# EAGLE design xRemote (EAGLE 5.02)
CAT_NR: 04; CLASS: 5HNc; LAST_EDIT: 11.09; SHORTNAME: DulM; SUBTITLE: Stromlaufplan; TITLE: xRemote - CapSense; USERNAME: Dullnig Michael

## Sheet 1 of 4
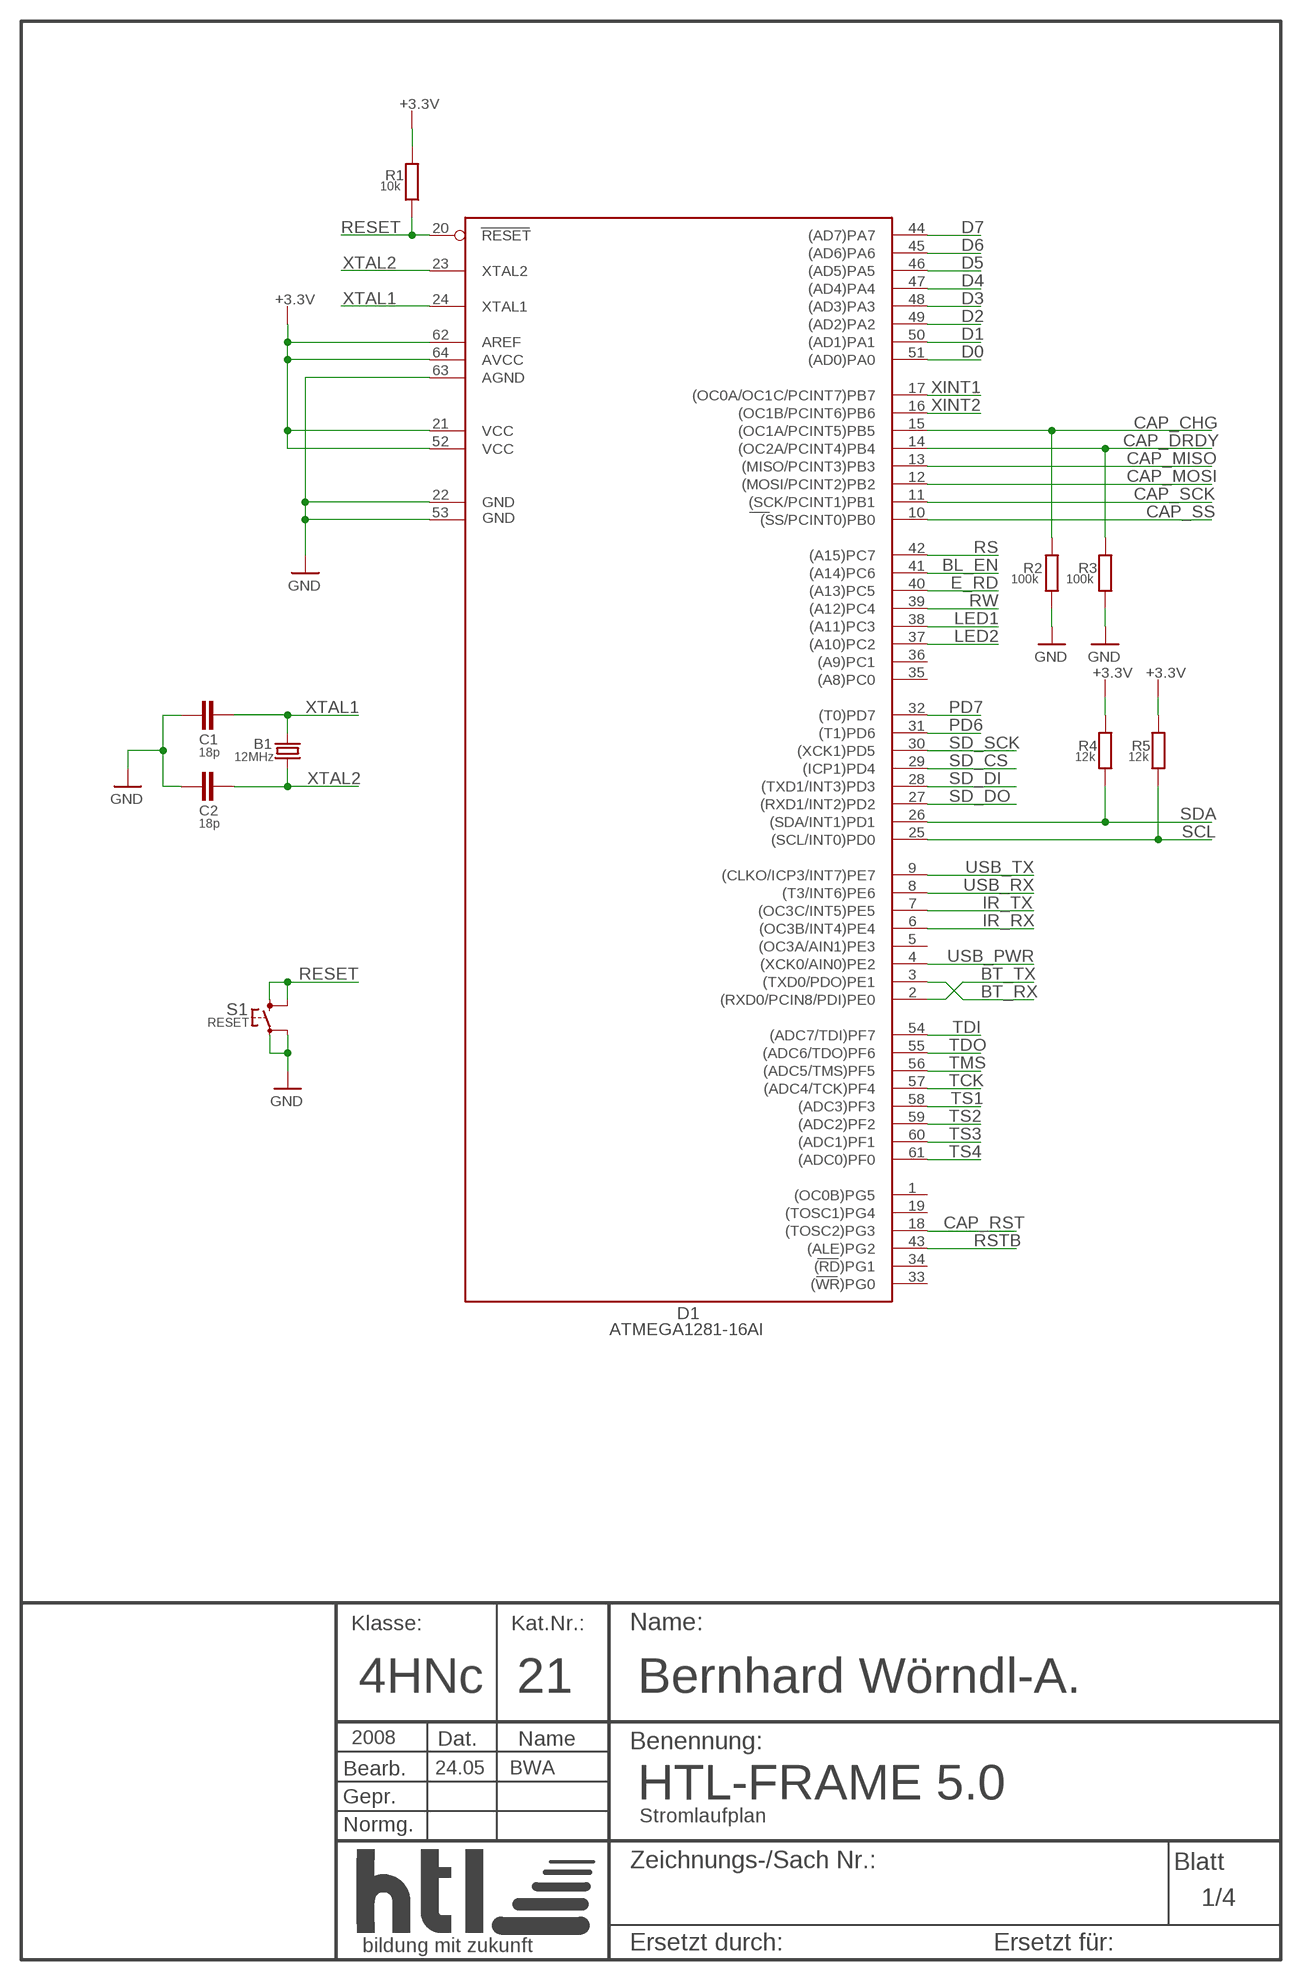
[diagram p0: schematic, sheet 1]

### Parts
B1  12MHz  CRYSTALHC49UP  [HC49UP]
C1  18p  C-EUC0805  [C0805]
C2  18p  C-EUC0805  [C0805]
D1  ATMEGA1281-16AI  ATMEGA2561-16AI  [TQFP64]
R1  10k  R-EU_M0805  [M0805]
R2  100k  R-EU_M1206  [M1206]
R3  100k  R-EU_M1206  [M1206]
R4  12k  R-EU_M1206  [M1206]
R5  12k  R-EU_M1206  [M1206]
S1  RESET  10-XX  [B3F-10XX]
U$1  HTL-FRAME-A4  [NOTHING]

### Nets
+3.3V: D1.21(VCC) D1.52(VCC1) D1.62(AREF) D1.64(AVCC) R1.2 R4.2 R5.2 ; also sheet 2,3,4
BL_EN: D1.41((A14)PC6) ; also sheet 3
BT_RX: D1.3((TXD0/PDO)PE1) ; also sheet 3
BT_TX: D1.2((RXD0/PCIN8/PDI)PE0) ; also sheet 3
CAP_CHG: D1.15((OC1A/PCINT5)PB5) R2.1 ; also sheet 4
CAP_DRDY: D1.14((OC2A/PCINT4)PB4) R3.1 ; also sheet 4
CAP_MISO: D1.13((MISO/PCINT3)PB3) ; also sheet 4
CAP_MOSI: D1.12((MOSI/PCINT2)PB2) ; also sheet 4
CAP_RST: D1.18((TOSC2)PG3) ; also sheet 4
CAP_SCK: D1.11((SCK/PCINT1)PB1) ; also sheet 4
CAP_SS: D1.10((SS/PCINT0)PB0) ; also sheet 4
D0: D1.51((AD0)PA0) ; also sheet 3
D1: D1.50((AD1)PA1) ; also sheet 3
D2: D1.49((AD2)PA2) ; also sheet 3
D3: D1.48((AD3)PA3) ; also sheet 3
D4: D1.47((AD4)PA4) ; also sheet 3
D5: D1.46((AD5)PA5) ; also sheet 3
D6: D1.45((AD6)PA6) ; also sheet 3
D7: D1.44((AD7)PA7) ; also sheet 3
E_RD: D1.40((A13)PC5) ; also sheet 3
GND: C1.1 C2.1 D1.22(GND) D1.53(GND1) D1.63(AGND) R2.2 R3.2 S1.3(P1) S1.4(P) ; also sheet 2,3,4
IR_RX: D1.6((OC3B/INT4)PE4) ; also sheet 4
IR_TX: D1.7((OC3C/INT5)PE5) ; also sheet 4
LED1: D1.38((A11)PC3) ; also sheet 3
LED2: D1.37((A10)PC2) ; also sheet 3
PD6: D1.31((T1)PD6) ; also sheet 3
PD7: D1.32((T0)PD7) ; also sheet 3
RESET: D1.20(RESET) R1.1 S1.1(S1) S1.2(S) ; also sheet 3
RS: D1.42((A15)PC7) ; also sheet 3
RSTB: D1.43((ALE)PG2) ; also sheet 3
RW: D1.39((A12)PC4) ; also sheet 3
SCL: D1.25((SCL/INT0)PD0) R5.1 ; also sheet 3
SD_CS: D1.29((ICP1)PD4) ; also sheet 3
SD_DI: D1.28((TXD1/INT3)PD3) ; also sheet 3
SD_DO: D1.27((RXD1/INT2)PD2) ; also sheet 3
SD_SCK: D1.30((XCK1)PD5) ; also sheet 3
SDA: D1.26((SDA/INT1)PD1) R4.1 ; also sheet 3
TCK: D1.57((ADC4/TCK)PF4) ; also sheet 3
TDI: D1.54((ADC7/TDI)PF7) ; also sheet 3
TDO: D1.55((ADC6/TDO)PF6) ; also sheet 3
TMS: D1.56((ADC5/TMS)PF5) ; also sheet 3
TS1: D1.58((ADC3)PF3) ; also sheet 3
TS2: D1.59((ADC2)PF2) ; also sheet 3
TS3: D1.60((ADC1)PF1) ; also sheet 3
TS4: D1.61((ADC0)PF0) ; also sheet 3
USB_PWR: D1.4((XCK0/AIN0)PE2) ; also sheet 3
USB_RX: D1.8((T3/INT6)PE6) ; also sheet 3
USB_TX: D1.9((CLKO/ICP3/INT7)PE7) ; also sheet 3
XINT1: D1.17((OC0A/OC1C/PCINT7)PB7) ; also sheet 3
XINT2: D1.16((OC1B/PCINT6)PB6) ; also sheet 3
XTAL1: B1.2 C1.2 D1.24(XTAL1)
XTAL2: B1.1 C2.2 D1.23(XTAL2)
Unconnected: D1.1((OC0B)PG5) D1.5((OC3A/AIN1)PE3) D1.19((TOSC1)PG4) D1.33((WR)PG0) D1.34((RD)PG1) D1.35((A8)PC0) D1.36((A9)PC1)

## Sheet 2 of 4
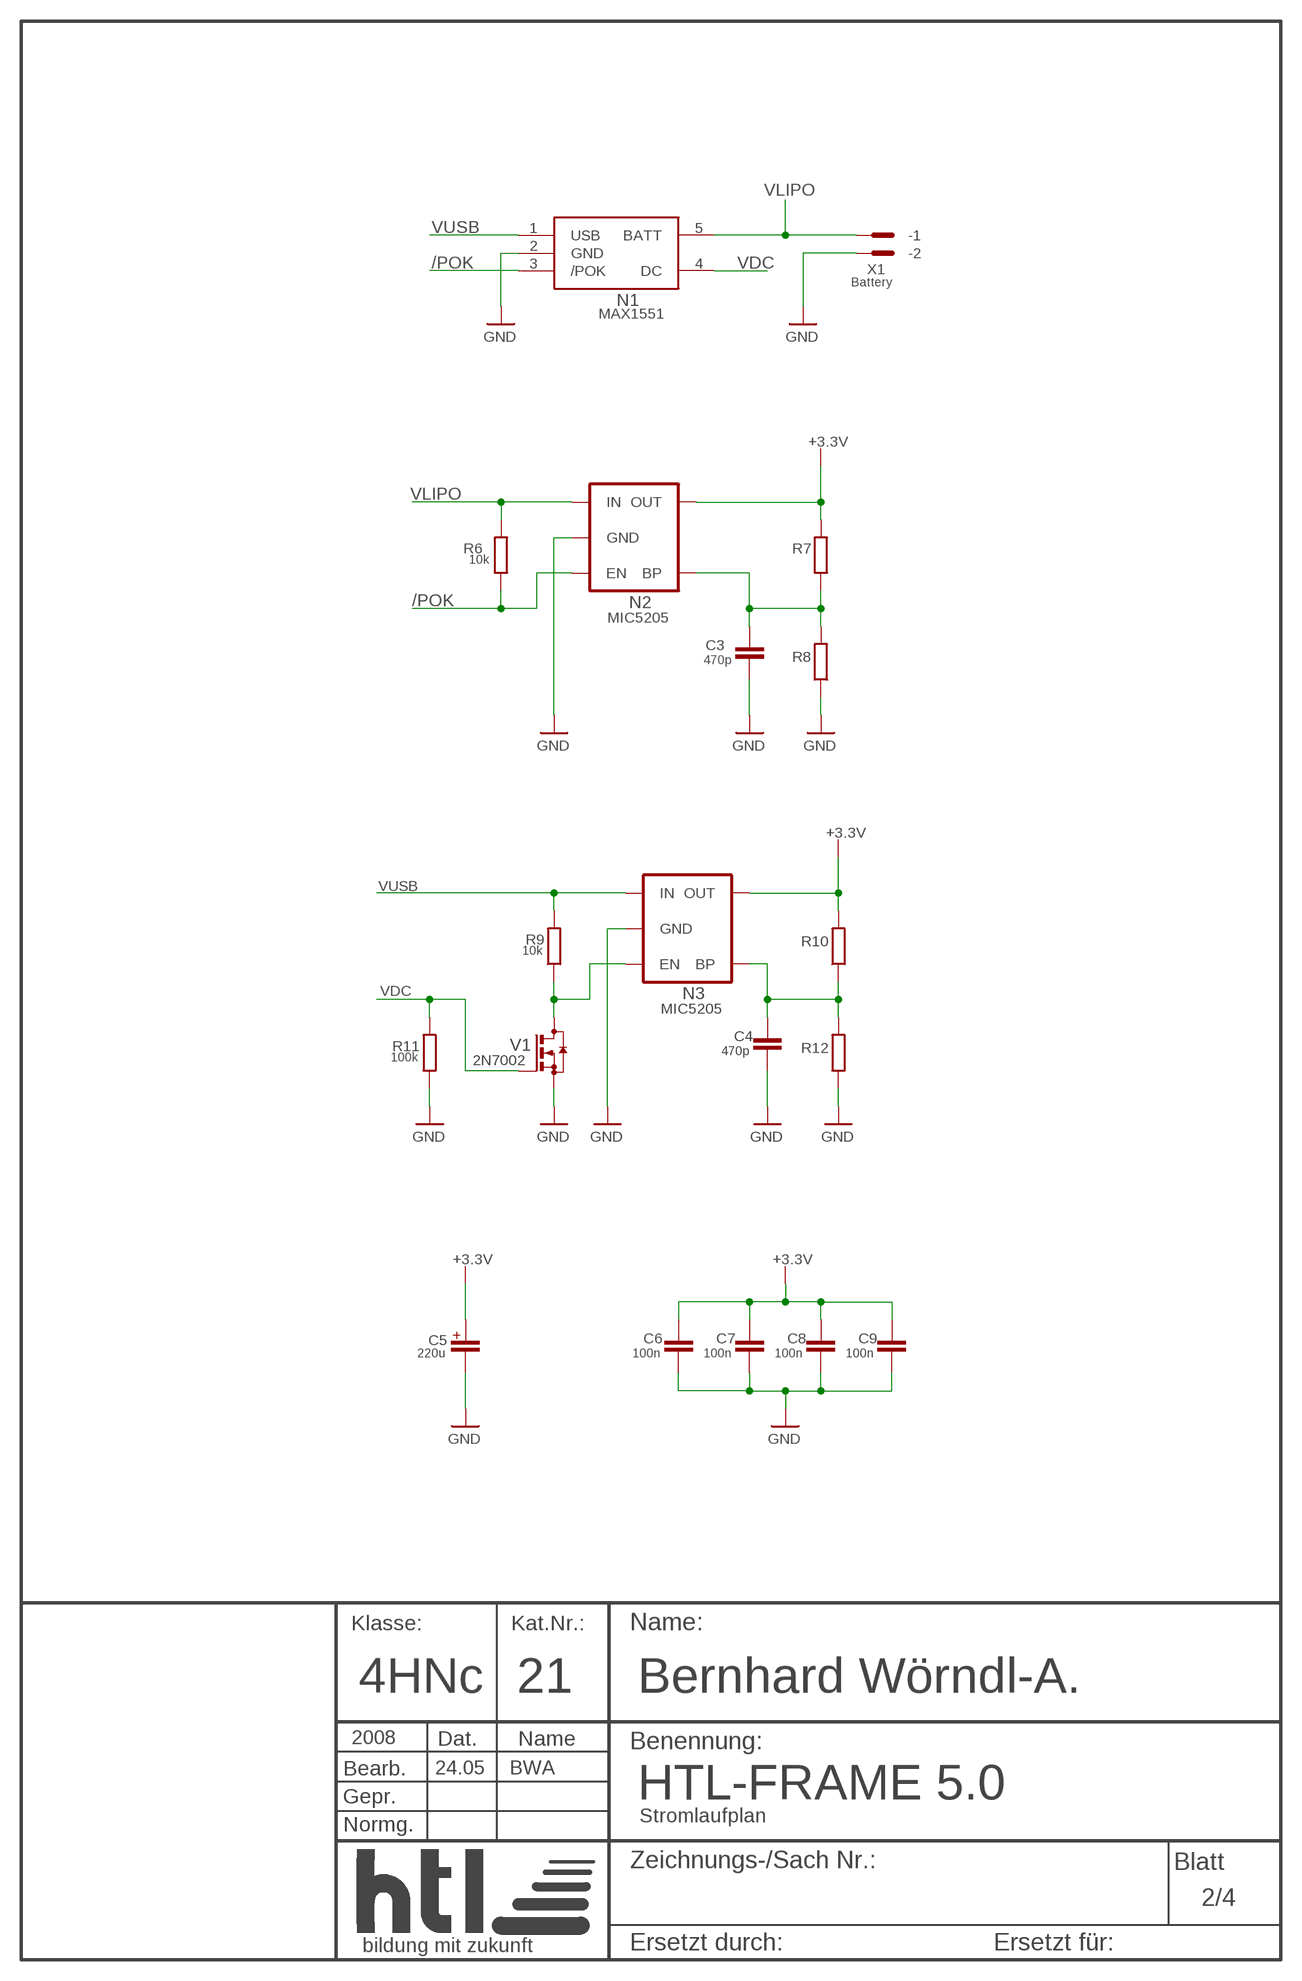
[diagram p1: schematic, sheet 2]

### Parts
C3  470p  C-EUC0805  [C0805]
C4  470p  C-EUC0805  [C0805]
C5  220u  CPOL-EUF  [PANASONIC_F]
C6  100n  C-EUC0805  [C0805]
C7  100n  C-EUC0805  [C0805]
C8  100n  C-EUC0805  [C0805]
C9  100n  C-EUC0805  [C0805]
N1  MAX1551  [SOT23-5]
N2  MIC5205  MIC5205SMD  [SOT23-5]
N3  MIC5205  MIC5205SMD  [SOT23-5]
R6  10k  R-EU_M1206  [M1206]
R7  R-EU_M0805  [M0805]
R8  R-EU_M0805  [M0805]
R9  10k  R-EU_M1206  [M1206]
R10  R-EU_M0805  [M0805]
R11  100k  R-EU_M1206  [M1206]
R12  R-EU_M0805  [M0805]
U$2  HTL-FRAME-A4  [NOTHING]
V1  2N7002  BSS123  [SOT23]
X1  Battery  CON_JST  [CON_JST]

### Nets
+3.3V: C5.+ C6.1 C7.1 C8.1 C9.1 N2.5(OUT) N3.5(OUT) R7.2 R10.2 ; also sheet 1,3,4
/POK: N1.3(/POK) N2.3(EN) R6.1
ENLIPO1: N3.3(EN) R9.1 V1.3(D)
GND: C3.2 C4.2 C5.- C6.2 C7.2 C8.2 C9.2 N1.2(GND) N2.2(GND) N3.2(GND) R8.1 R11.1 R12.1 V1.2(S) X1.P2(-2) ; also sheet 1,3,4
N$48: C4.1 N3.4(BP) R10.1 R12.2
N$50: C3.1 N2.4(BP) R7.1 R8.2
VDC: N1.4(DC) R11.2 V1.1(G) ; also sheet 3
VLIPO: N1.5(BATT) N2.1(IN) R6.2 X1.P1(-1)
VUSB: N1.1(USB) N3.1(IN) R9.2 ; also sheet 3

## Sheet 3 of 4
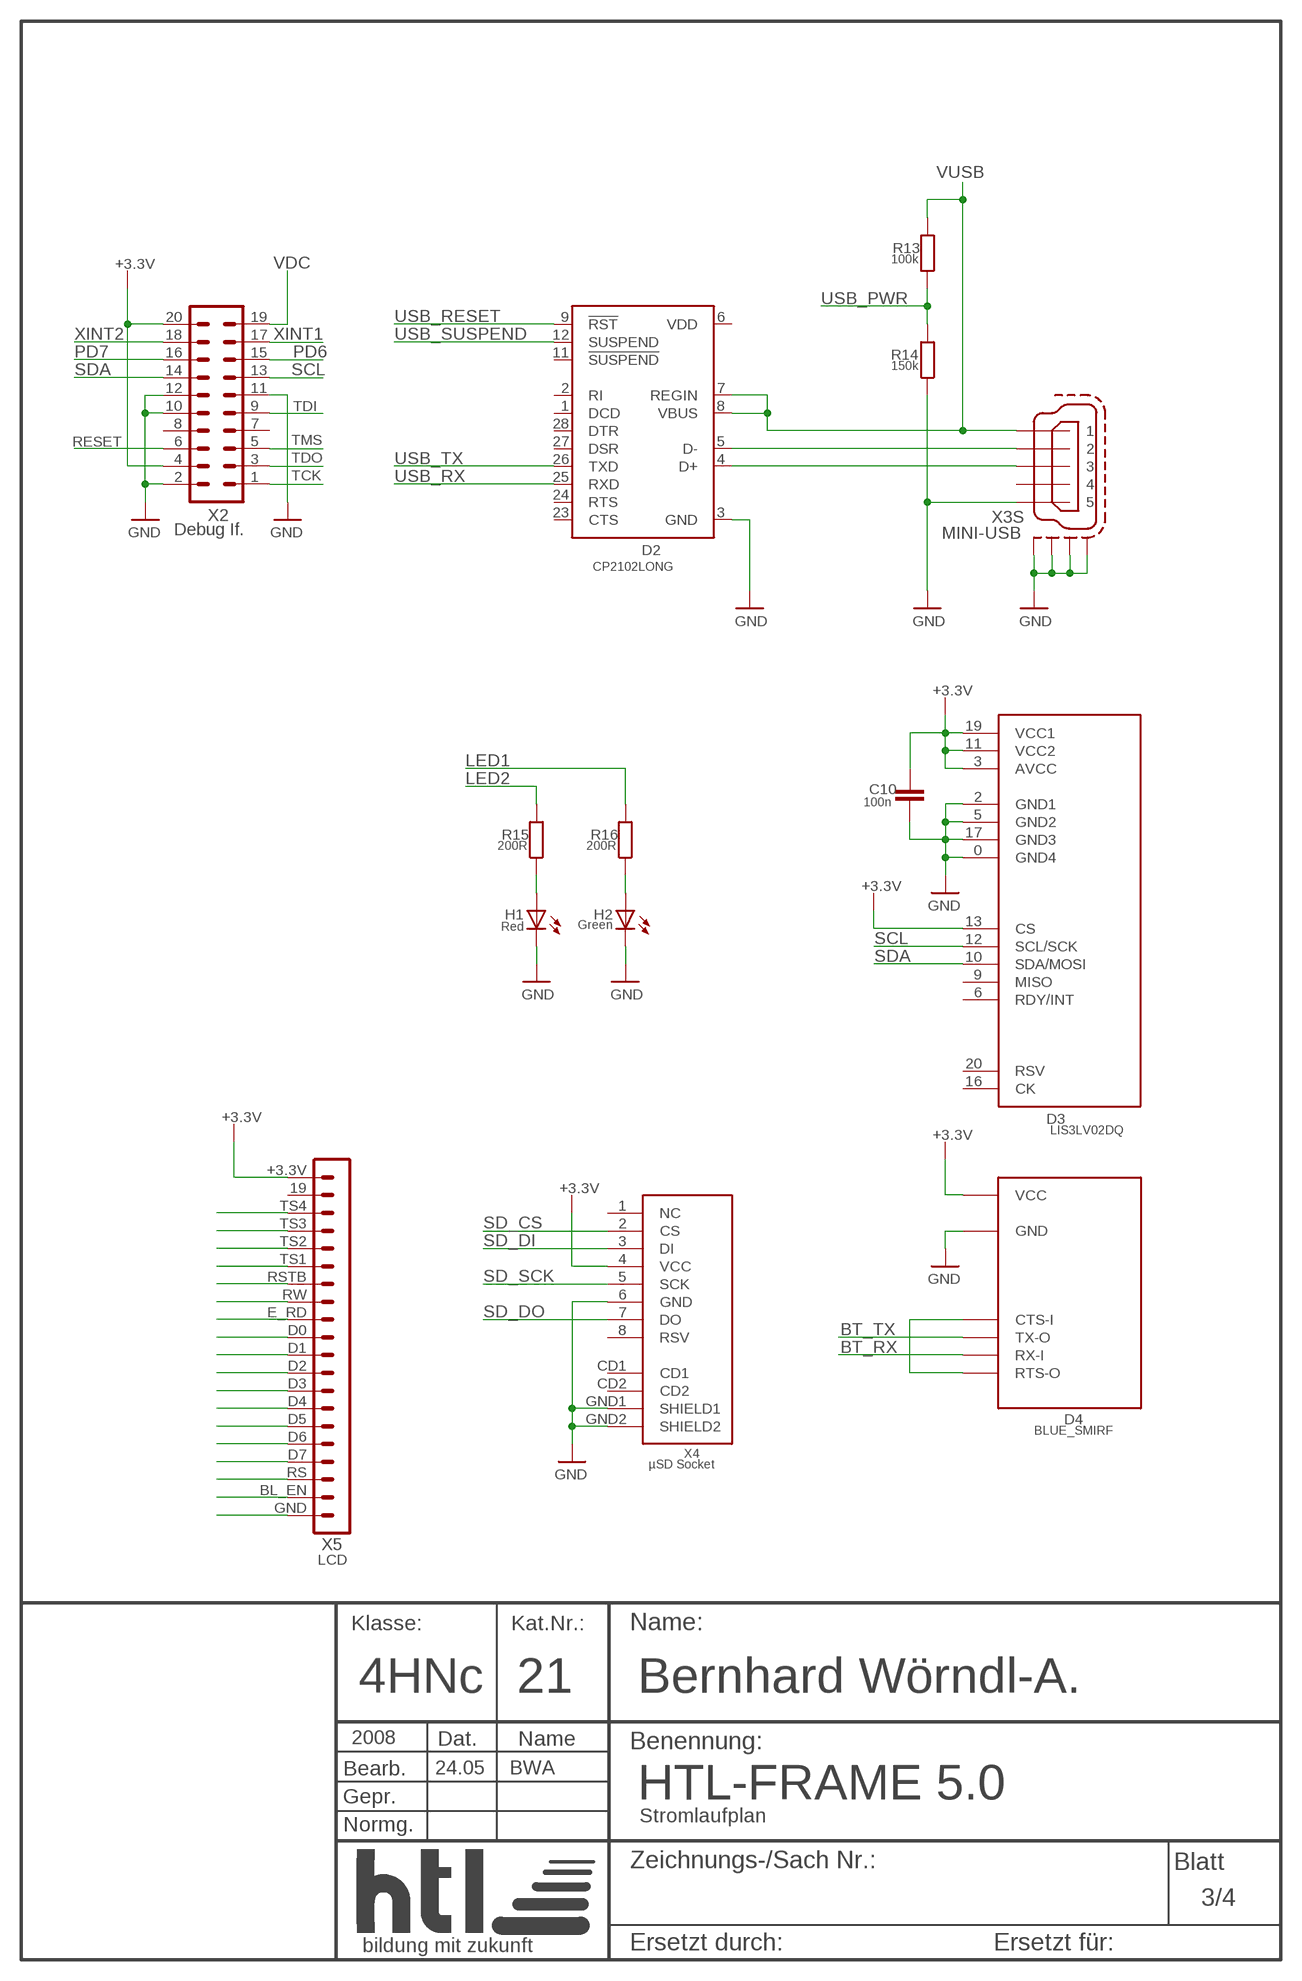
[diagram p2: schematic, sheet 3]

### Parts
C10  100n  C-EUC0805  [C0805]
D2  CP2102LONG  [MYLIB_MLP28-LONG]
D3  LIS3LV02DQ  [QFPN28]
D4  BLUE_SMIRF  BLUE_SMIRFSMALL  [BLUE_SMIRF_SMALL]
H1  Red  LEDCHIPLED_0805  [CHIPLED_0805]
H2  Green  LEDCHIPLED_0805  [CHIPLED_0805]
R13  100k  R-EU_M0805  [M0805]
R14  150k  R-EU_M0805  [M0805]
R15  200R  R-EU_M0805  [M0805]
R16  200R  R-EU_M0805  [M0805]
U$3  HTL-FRAME-A4  [NOTHING]
X2  Debug If.  CON_DEBUG  [CONDEBUG]
X3  MINI-USB  MINI-USB-SCHIELD-32005-301  [32005-301]
X4  µSD Socket  USD-SOCKETUSD  [USD-SOCKET-PP]
X5  LCD  CON_CFAX_SPEC  [CON_CFAX_SPEC]

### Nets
+3.3V: C10.1 D3.3(AVCC) D3.11(VCC2) D3.13(CS) D3.19(VCC1) D4.PWR(VCC) X2.4 X2.20 X4.4(VCC) X5.+3.3V ; also sheet 1,2,4
BL_EN: X5.BL_EN ; also sheet 1
BT_RX: D4.RX-I ; also sheet 1
BT_TX: D4.TX-O ; also sheet 1
D0: X5.D0 ; also sheet 1
D1: X5.D1 ; also sheet 1
D2: X5.D2 ; also sheet 1
D3: X5.D3 ; also sheet 1
D4: X5.D4 ; also sheet 1
D5: X5.D5 ; also sheet 1
D6: X5.D6 ; also sheet 1
D7: X5.D7 ; also sheet 1
D+: D2.5(D-) X3.2
D-: D2.4(D+) X3.3
E_RD: X5.E_RD ; also sheet 1
GND: C10.2 D2.3(GND) D3.0(GND4) D3.2(GND1) D3.5(GND2) D3.17(GND3) D4.GND H1.C H2.C R14.1 X2.2 X2.10 X2.11 X2.12 X3.5 X3.M1(S:S1) X3.M2(S:S2) X3.M3(S:S3) X3.M4(S:S4) X4.6(GND) X4.GND1(SHIELD1) X4.GND2(SHIELD2) X5.GND ; also sheet 1,2,4
LED1: R16.2 ; also sheet 1
LED2: R15.2 ; also sheet 1
N$1: H2.A R16.1
N$5: D4.CTS-I D4.RTS-O
N$6: H1.A R15.1
PD6: X2.15 ; also sheet 1
PD7: X2.16 ; also sheet 1
RESET: X2.6 ; also sheet 1
RS: X5.RS ; also sheet 1
RSTB: X5.RSTB ; also sheet 1
RW: X5.RW ; also sheet 1
SCL: D3.12(SCL/SCK) X2.13 ; also sheet 1
SD_CS: X4.2(CS) ; also sheet 1
SD_DI: X4.3(DI) ; also sheet 1
SD_DO: X4.7(DO) ; also sheet 1
SD_SCK: X4.5(SCK) ; also sheet 1
SDA: D3.10(SDA/MOSI) X2.14 ; also sheet 1
TCK: X2.1 ; also sheet 1
TDI: X2.9 ; also sheet 1
TDO: X2.3 ; also sheet 1
TMS: X2.5 ; also sheet 1
TS1: X5.TS1 ; also sheet 1
TS2: X5.TS2 ; also sheet 1
TS3: X5.TS3 ; also sheet 1
TS4: X5.TS4 ; also sheet 1
USB_PWR: R13.1 R14.2 ; also sheet 1
USB_RESET: D2.9(!RST)
USB_RX: D2.25(RXD) ; also sheet 1
USB_SUSPEND: D2.12(SUSPEND)
USB_TX: D2.26(TXD) ; also sheet 1
VDC: X2.19 ; also sheet 2
VUSB: D2.7(REGIN) D2.8(VBUS) R13.2 X3.1 ; also sheet 2
XINT1: X2.17 ; also sheet 1
XINT2: X2.18 ; also sheet 1
Unconnected: D2.1(DCD) D2.2(RI) D2.6(VDD) D2.11(!SUSPEND) D2.23(CTS) D2.24(RTS) D2.27(DSR) D2.28(DTR) D3.6(RDY/INT) D3.9(MISO) D3.16(CK) D3.20(RSV) X2.7 X2.8 X3.4 X4.1(NC) X4.8(RSV) X4.CD1 X4.CD2 X5.19

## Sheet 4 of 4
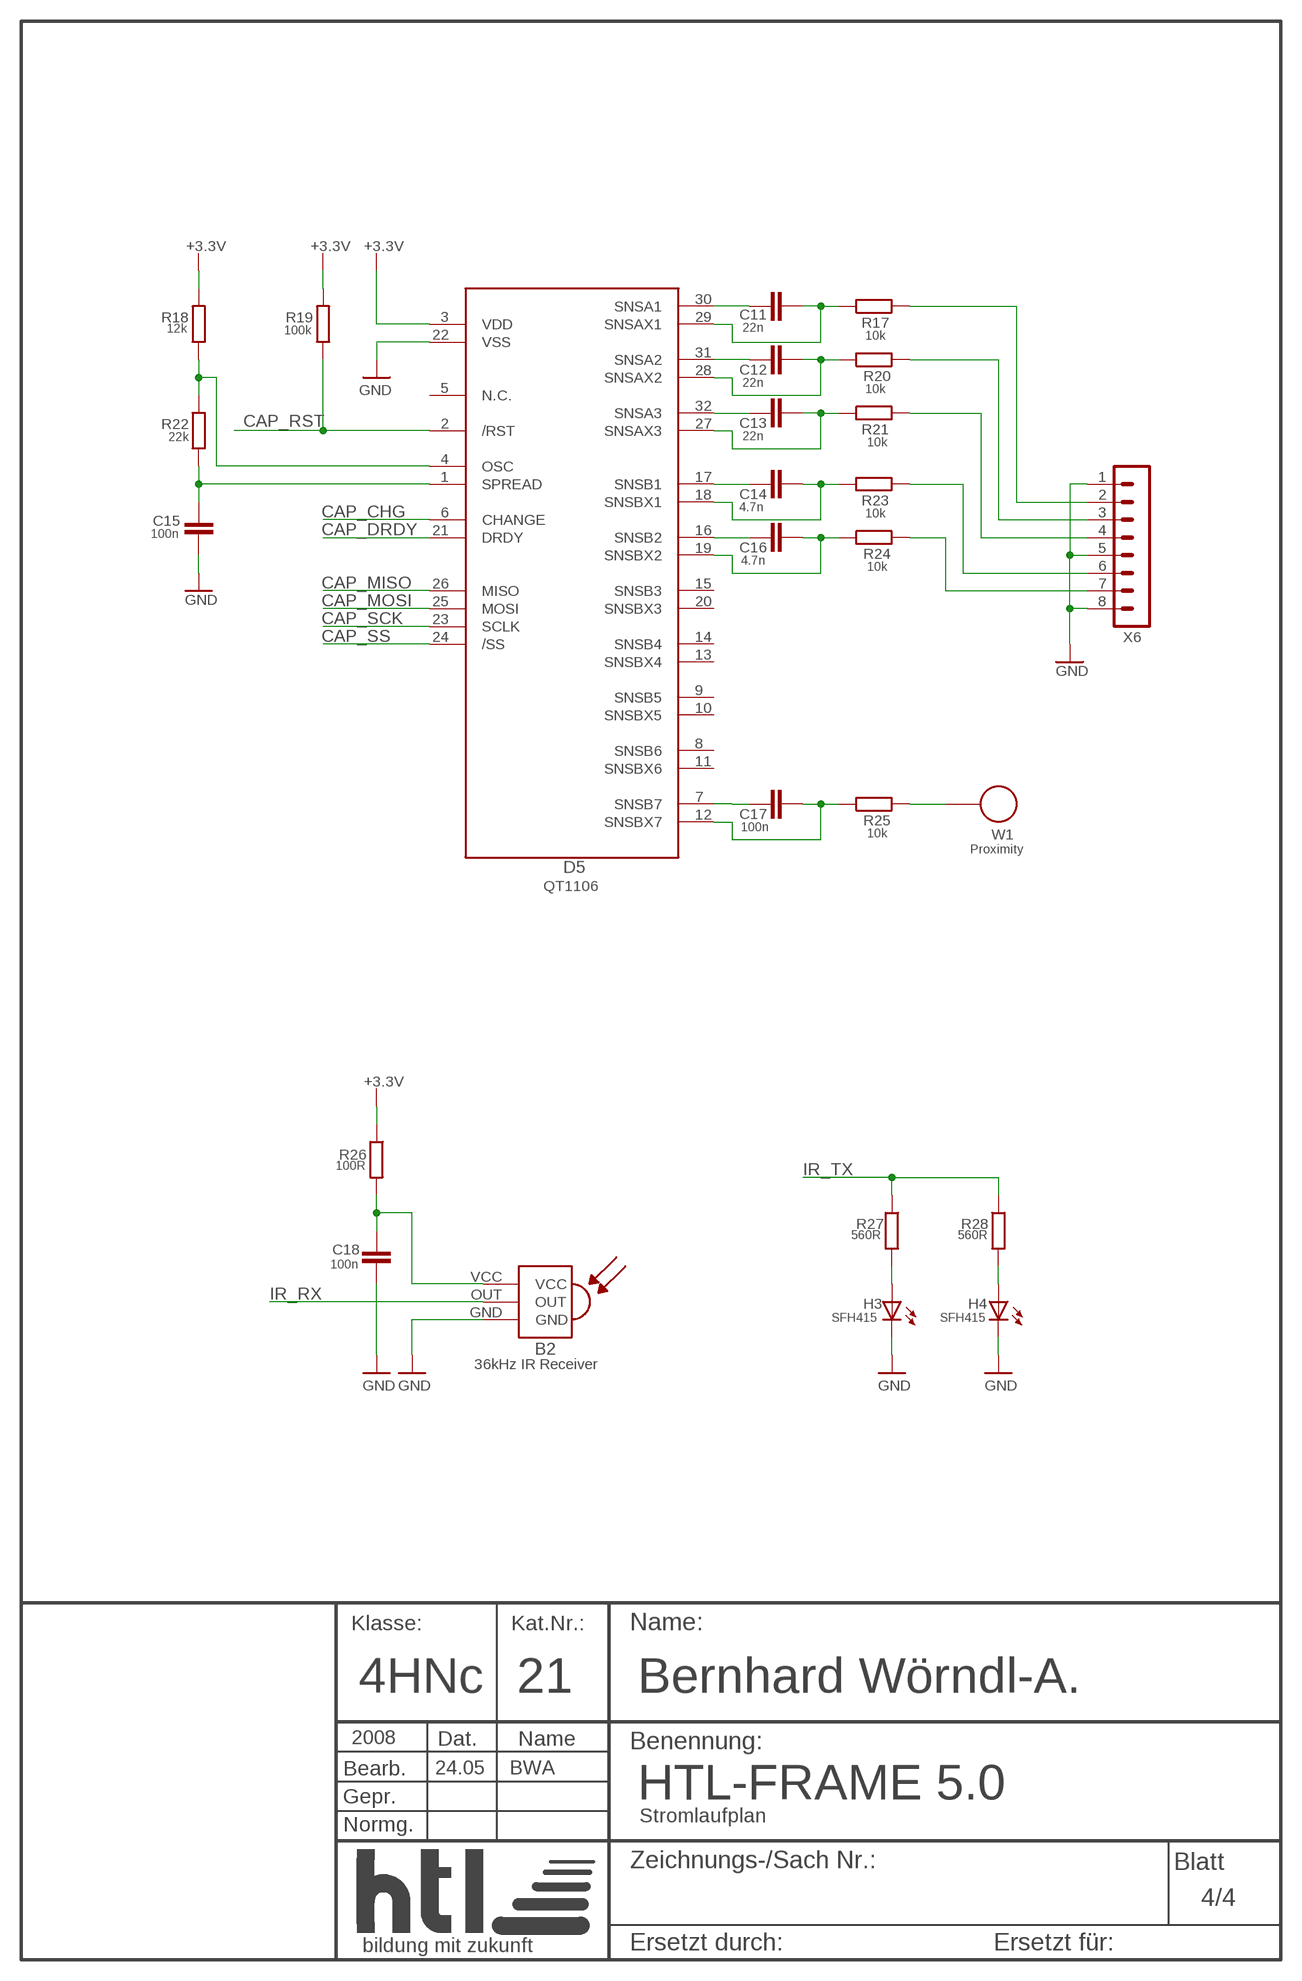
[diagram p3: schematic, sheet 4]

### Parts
B2  36kHz IR Receiver  GP1UX310QSB  [GP1UX310QS]
C11  22n  C-EUC0805  [C0805]
C12  22n  C-EUC0805  [C0805]
C13  22n  C-EUC0805  [C0805]
C14  4.7n  C-EUC0805  [C0805]
C15  100n  C-EUC0805  [C0805]
C16  4.7n  C-EUC0805  [C0805]
C17  100n  C-EUC0805  [C0805]
C18  100n  C-EUC0805  [C0805]
D5  QT1106  [MLF32]
H3  SFH415  LED5MM  [LED5MM]
H4  SFH415  LED5MM  [LED5MM]
R17  10k  R-EU_M1206  [M1206]
R18  12k  R-EU_M1206  [M1206]
R19  100k  R-EU_M1206  [M1206]
R20  10k  R-EU_M1206  [M1206]
R21  10k  R-EU_M1206  [M1206]
R22  22k  R-EU_M1206  [M1206]
R23  10k  R-EU_M1206  [M1206]
R24  10k  R-EU_M1206  [M1206]
R25  10k  R-EU_M1206  [M1206]
R26  100R  R-EU_M0805  [M0805]
R27  560R  R-EU_M0805  [M0805]
R28  560R  R-EU_M0805  [M0805]
U$4  HTL-FRAME-A4  [NOTHING]
W1  Proximity  CAP_BTN  [CAP_BTN]
X6  FPC  MA08-1  [MA08-1]

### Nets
+3.3V: D5.3(VDD) R18.2 R19.2 R26.1 ; also sheet 1,2,3
CAP_CHG: D5.6(CHANGE) ; also sheet 1
CAP_DRDY: D5.21(DRDY) ; also sheet 1
CAP_MISO: D5.26(MISO) ; also sheet 1
CAP_MOSI: D5.25(MOSI) ; also sheet 1
CAP_RST: D5.2(/RST) R19.1 ; also sheet 1
CAP_SCK: D5.23(SCLK) ; also sheet 1
CAP_SS: D5.24(/SS) ; also sheet 1
GND: B2.GND C15.1 C18.2 D5.22(VSS) H3.K(C) H4.K(C) X6.1 X6.5 X6.8 ; also sheet 1,2,3
IR_RX: B2.OUT ; also sheet 1
IR_TX: R27.1 R28.1 ; also sheet 1
N$2: H3.A R27.2
N$3: H4.A R28.2
N$4: D5.4(OSC) R18.1 R22.2
N$7: C17.2 D5.12(SNSBX7) R25.1
N$8: C11.2 D5.29(SNSAX1) R17.1
N$9: C11.1 D5.30(SNSA1)
N$10: C12.1 D5.31(SNSA2)
N$11: C12.2 D5.28(SNSAX2) R20.1
N$12: C13.1 D5.32(SNSA3)
N$13: C13.2 D5.27(SNSAX3) R21.1
N$14: C14.1 D5.17(SNSB1)
N$15: C14.2 D5.18(SNSBX1) R23.1
N$16: C17.1 D5.7(SNSB7)
N$17: C16.1 D5.16(SNSB2)
N$18: C16.2 D5.19(SNSBX2) R24.1
N$19: R25.2 W1.P$1
N$21: C15.2 D5.1(SPREAD) R22.1
N$29: R17.2 X6.2
N$30: R20.2 X6.3
N$31: R21.2 X6.4
N$32: R23.2 X6.6
N$33: R24.2 X6.7
VCC: B2.VCC C18.1 R26.2
Unconnected: D5.5(N.C.) D5.8(SNSB6) D5.9(SNSB5) D5.10(SNSBX5) D5.11(SNSBX6) D5.13(SNSBX4) D5.14(SNSB4) D5.15(SNSB3) D5.20(SNSBX3)

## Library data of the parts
B1 = AVRRemote:CRYSTAL: CRYSTAL
B2 = AVRRemote:GP1UX310QS
C1-C4 C6-C9 C11-C18 = AVRRemote:C-EU: CAPACITOR, European symbol
C5 = AVRRemote:CPOL-EU: POLARIZED CAPACITOR, European symbol
C10 = xRemote:C-EU: CAPACITOR, European symbol
D1 = AVRRemote:ATMEGA2561*: MICROCONTROLLER 256 Kbytes FLASH 4 Kbytes EEPROM 8 Kbytes SRAM 54 General Purpose I/O pins 6-channels 16-bit PWM 2 x Serial USARTs 8-channels 10-bit A/D
D2 = xRemote:CP2102
D3 = xRemote:LIS3LV02DQ
D4 = AVRRemote:BLUE_SMIRF
D5 = AVRRemote:QT1106
H1 H2 = xRemote:LED: LED
H3 H4 = AVRRemote:LED: LED
N1 = AVRRemote:MAX1551
N2 N3 = AVRRemote:MIC5205: Voltage Regulator LDO Standard 150mA LDO voltage regulator in SOT-23 layout. Micrel part MIC5205. BP (by-pass) pin is used to lower output noise with 470pF cap.
R1-R28 = AVRRemote:R-EU_: RESISTOR, European symbol
S1 = xRemote:10-XX: OMRON SWITCH
U$1-U$4 = HTL-FRAMES-5_BWA:HTL-FRAME-A4: HTL - Frame A4; CAT_NR: 21; CLASS: 4HNc; LAST_EDIT: 24.05; SHORTNAME: BWA; SUBTITLE: Stromlaufplan; TITLE: HTL-FRAME 5.0; USERNAME: Bernhard Wörndl-A.; YEAR: 2008
V1 = AVRRemote:BSS123: N-CHANNEL MOS FET
W1 = xRemote:CAP_BTN
X1 = xRemote:CON_JST
X2 = AVRRemote:CON_DEBUG: PIN HEADER
X3 = xRemote:MINI-USB-SCHIELD-: MINI USB-B Conector Source: www.cypressindustries.com
X4 = AVRRemote:USD-SOCKET: microSD Socket Push-push type uSD socket. Schematic element and footprint production proven. Spark Fun Electronics SKU : PRT-00127. tDoc lines correctly indicate media card edge positions when inserting (unlocked, locked, depressed).
X5 = AVRRemote:CON_CFAX_SPEC: PIN HEADER
X6 = xRemote:MA08-1: PIN HEADER

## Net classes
1 GND: width 0.305 mm
2 +5V: width 0.305 mm

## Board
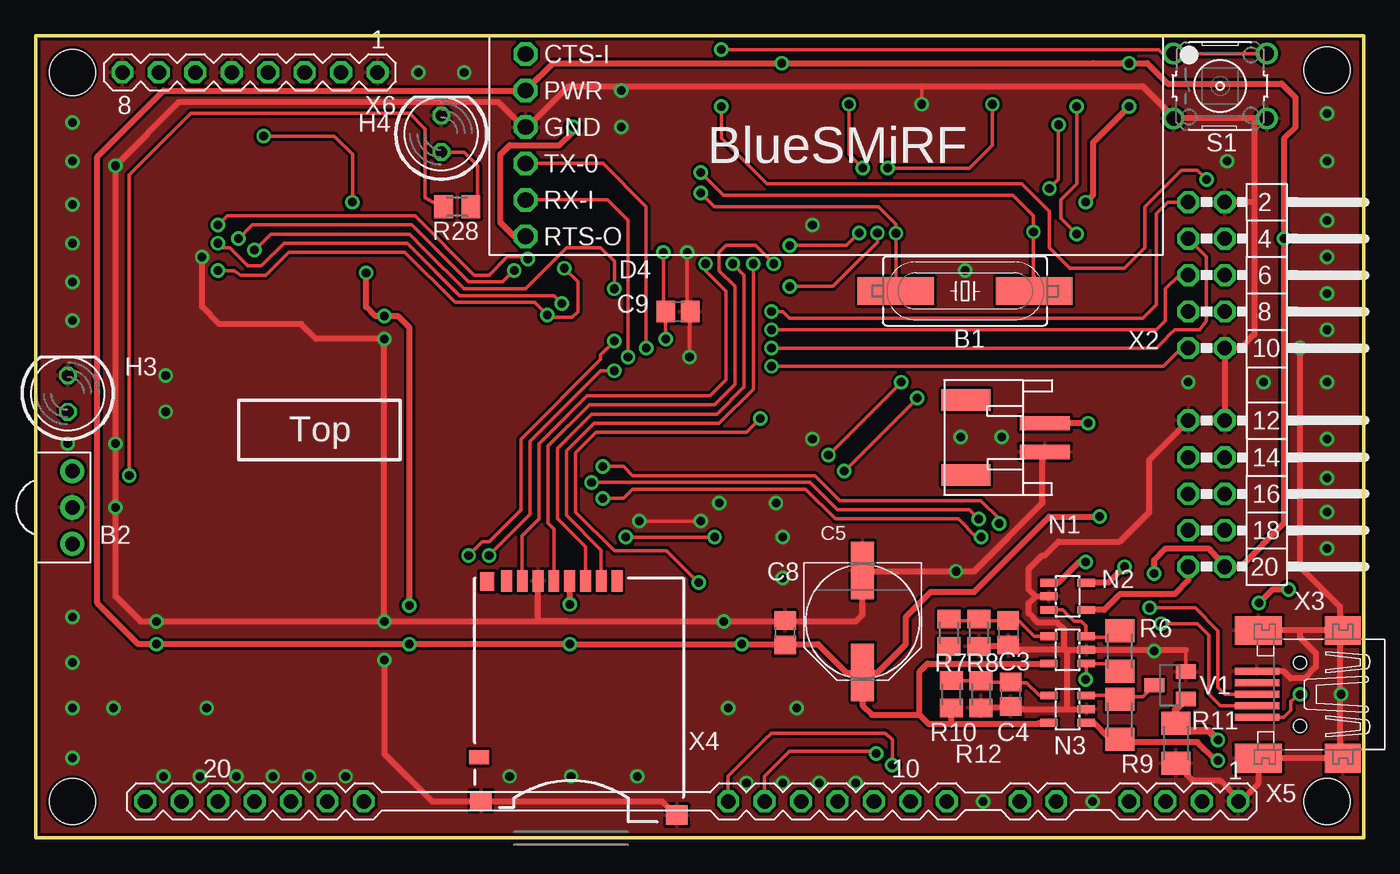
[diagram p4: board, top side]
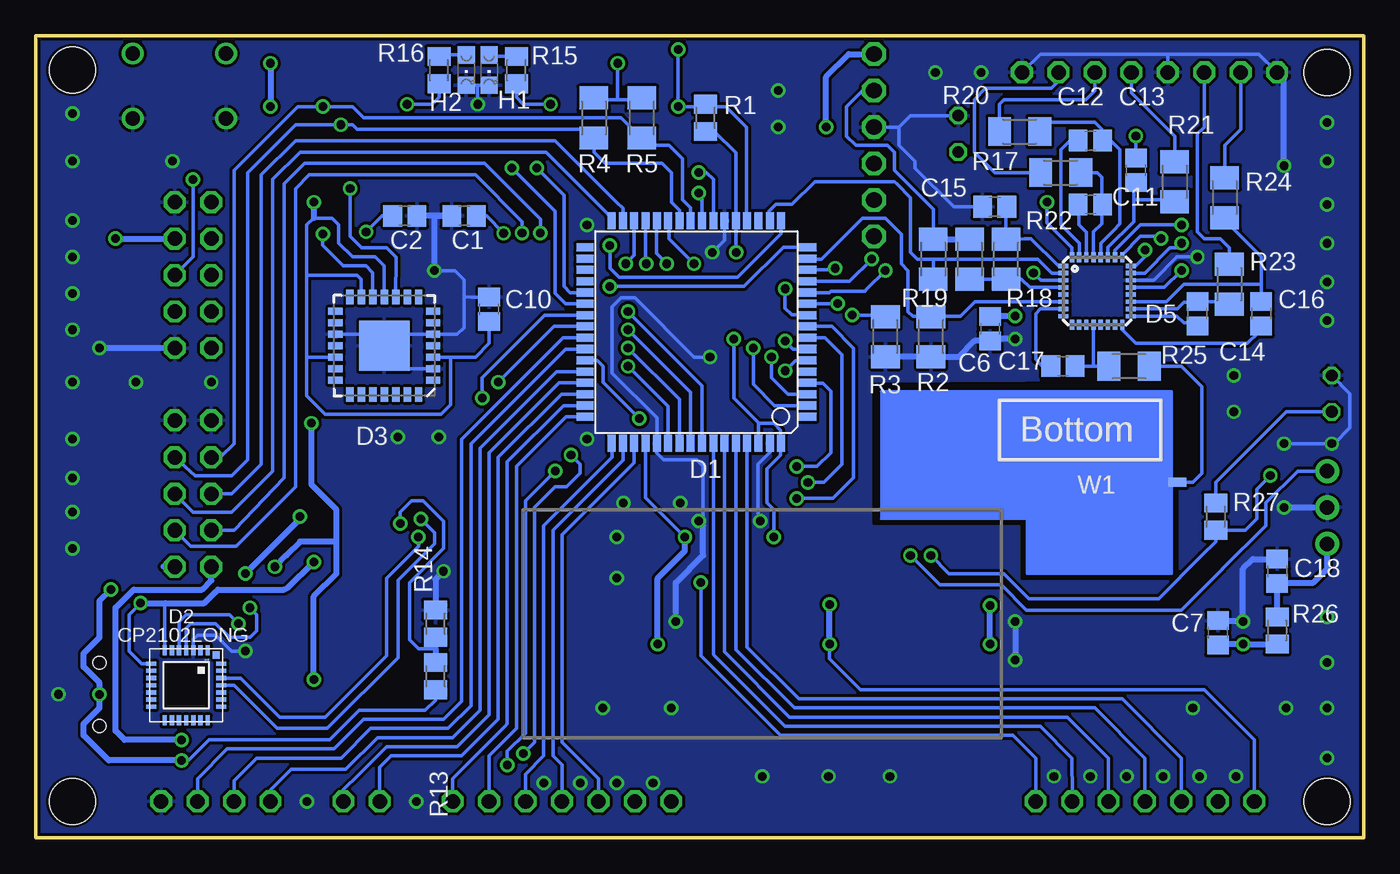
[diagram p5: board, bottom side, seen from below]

Size 92.55 x 55.88 mm. Coordinates in mm from the lower left corner, seen from the top.
Outline: 0,0 92.55,0 92.55,55.88 0,55.88 0,0
Copper layers (1+16): Top 0.035mm / dielectric 1.6mm / Bottom 0.035mm
Design rules "batchpcb *": minimum track width 8mil, minimum drill 0.4mm, track to track 8mil, track to pad 8mil, pad to pad 6mil, via to via 8mil, smd to smd 8mil, copper to edge 8mil, drill to drill 10mil, minimum pad ring 8mil, minimum via ring 0.2mm, stop-mask expansion 4mil, vias tented up to drill 18mil, thermal gap 8mil
Holes 3.2 mm at 2.54,2.54 90.01,2.54 90.01,53.5 2.54,53.34
bRestrict: area 13,18.1 to 34.1,31.8

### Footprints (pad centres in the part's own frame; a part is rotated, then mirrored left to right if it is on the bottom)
HC49UP = smd 5.334 x 1.93: 1 -4.826,0; 2 4.826,0
GP1UX310QS = drill 1 pad 1.676 round: GND 0,2.54; OUT 0,5.08; VCC 0,0
C0805 = smd 1.3 x 1.5: 1 -0.85,0; 2 0.85,0
PANASONIC_F = smd 4 x 1.6: + 3.55,0; - -3.55,0
TQFP64 = smd 1.194 x 0.559: 1 -7.76,5.905; 2 -7.76,5.118; 3 -7.76,4.331; 4 -7.76,3.543; 5 -7.76,2.756; 6 -7.76,1.968; 7 -7.76,1.181; 8 -7.76,0.394; 9 -7.76,-0.394; 10 -7.76,-1.181; 11 -7.76,-1.968; 12 -7.76,-2.756; 13 -7.76,-3.543; 14 -7.76,-4.331; 15 -7.76,-5.118; 16 -7.76,-5.905; 33 7.76,-5.905; 34 7.76,-5.118; 35 7.76,-4.331; 36 7.76,-3.543; 37 7.76,-2.756; 38 7.76,-1.968; 39 7.76,-1.181; 40 7.76,-0.394; 41 7.76,0.394; 42 7.76,1.181; 43 7.76,1.968; 44 7.76,2.756; 45 7.76,3.543; 46 7.76,4.331; 47 7.76,5.118; 48 7.76,5.905 | smd 0.559 x 1.194: 17 -5.905,-7.76; 18 -5.118,-7.76; 19 -4.331,-7.76; 20 -3.543,-7.76; 21 -2.756,-7.76; 22 -1.968,-7.76; 23 -1.181,-7.76; 24 -0.394,-7.76; 25 0.394,-7.76; 26 1.181,-7.76; 27 1.968,-7.76; 28 2.756,-7.76; 29 3.543,-7.76; 30 4.331,-7.76; 31 5.118,-7.76; 32 5.905,-7.76; 49 5.905,7.76; 50 5.118,7.76; 51 4.331,7.76; 52 3.543,7.76; 53 2.756,7.76; 54 1.968,7.76; 55 1.181,7.76; 56 0.394,7.76; 57 -0.394,7.76; 58 -1.181,7.76; 59 -1.968,7.76; 60 -2.756,7.76; 61 -3.543,7.76; 62 -4.331,7.76; 63 -5.118,7.76; 64 -5.905,7.76
MYLIB_MLP28-LONG = smd 0.7 x 0.3: 1 -2.45,1.5; 2 -2.45,1; 3 -2.45,0.5; 4 -2.45,0; 5 -2.45,-0.5; 6 -2.45,-1; 7 -2.45,-1.5; 15 2.45,-1.5; 16 2.45,-1; 17 2.45,-0.5; 18 2.45,0; 19 2.45,0.5; 20 2.45,1; 21 2.45,1.5 | smd 0.3 x 0.7: 8 -1.5,-2.45; 9 -1,-2.45; 10 -0.5,-2.45; 11 0,-2.45; 12 0.5,-2.45; 13 1,-2.45; 14 1.5,-2.45; 22 1.5,2.45; 23 1,2.45; 24 0.5,2.45; 25 0,2.45; 26 -0.5,2.45; 27 -1,2.45; 28 -1.5,2.45 | smd 0.5 x 0.5: GND@1 -2.1,2.1
QFPN28 = smd 3.5 x 3.5: 0 0,0 | smd 1 x 0.5: 1 -3.4,2.4; 2 -3.4,1.6; 3 -3.4,0.8; 4 -3.4,0; 5 -3.4,-0.8; 6 -3.4,-1.6; 7 -3.4,-2.4; 15 3.4,-2.4; 16 3.4,-1.6; 17 3.4,-0.8; 18 3.4,0; 19 3.4,0.8; 20 3.4,1.6; 21 3.4,2.4 | smd 0.5 x 1: 8 -2.4,-3.4; 9 -1.6,-3.4; 10 -0.8,-3.4; 11 0,-3.4; 12 0.8,-3.4; 13 1.6,-3.4; 14 2.4,-3.4; 22 2.4,3.4; 23 1.6,3.4; 24 0.8,3.4; 25 0,3.4; 26 -0.8,3.4; 27 -1.6,3.4; 28 -2.4,3.4
BLUE_SMIRF_SMALL = drill 1.1 octagon: CTS-I 0,6.35; GND 0,1.27; PWR 0,3.81; RTS-O 0,-6.35; RX-I 0,-3.81; TX-O 0,-1.27
MLF32 = smd 0.7 x 0.3: 1 -2.35,1.75; 2 -2.35,1.25; 3 -2.35,0.75; 4 -2.35,0.25; 5 -2.35,-0.25; 6 -2.35,-0.75; 7 -2.35,-1.25; 8 -2.35,-1.75; 17 2.35,-1.75; 18 2.35,-1.25; 19 2.35,-0.75; 20 2.35,-0.25; 21 2.35,0.25; 22 2.35,0.75; 23 2.35,1.25; 24 2.35,1.75 | smd 0.3 x 0.7: 9 -1.75,-2.35; 10 -1.25,-2.35; 11 -0.75,-2.35; 12 -0.25,-2.35; 13 0.25,-2.35; 14 0.75,-2.35; 15 1.25,-2.35; 16 1.75,-2.35; 25 1.75,2.35; 26 1.25,2.35; 27 0.75,2.35; 28 0.25,2.35; 29 -0.25,2.35; 30 -0.75,2.35; 31 -1.25,2.35; 32 -1.75,2.35
CHIPLED_0805 = smd 1.2 x 1.2: A 0,-1.05; C 0,1.05
LED5MM = drill 0.813 octagon: A -1.27,0; K 1.27,0
SOT23-5 = smd 0.55 x 1.2: 1 -0.95,-1.3; 2 0,-1.3; 3 0.95,-1.3; 4 0.95,1.3; 5 -0.95,1.3
M0805 = smd 1.3 x 1.6: 1 -0.95,0; 2 0.95,0
M1206 = smd 1.6 x 2: 1 -1.4,0; 2 1.4,0
B3F-10XX = drill 1 pad 1.524 round: 1 -3.251,2.261; 2 3.251,2.261; 3 -3.251,-2.261; 4 3.251,-2.261
SOT23 = smd 1 x 1.4: 1 -0.95,-1.1; 2 0.95,-1.1; 3 0,1.1
CAP_BTN = smd 1.27 x 0.635: P$1 -10.5,0
CON_JST = smd 1 x 3.5: P1 0,0; P2 2,0 | smd 1.5 x 3.4: P$3 -1.6,-5.5; P$4 3.6,-5.5
CONDEBUG = drill 1.016 octagon: 1 -13.97,-1.27; 2 -13.97,1.27; 3 -11.43,-1.27; 4 -11.43,1.27; 5 -8.89,-1.27; 6 -8.89,1.27; 7 -6.35,-1.27; 8 -6.35,1.27; 9 -3.81,-1.27; 10 -3.81,1.27; 11 1.23,-1.27; 12 1.23,1.27; 13 3.81,-1.27; 14 3.81,1.27; 15 6.35,-1.27; 16 6.35,1.27; 17 8.89,-1.27; 18 8.89,1.27; 19 11.43,-1.27; 20 11.43,1.27
32005-301 = smd 3.1 x 0.5: 1 3,1.6; 2 3,0.8; 3 3,0; 4 3,-0.8; 5 3,-1.6 | smd 2.5 x 2: M1 -3,-4.45; M2 -3,4.45 | smd 3.3 x 2: M3 2.9,4.45; M4 2.9,-4.45 | hole 0.9: 0,2.2; 0,-2.2
USD-SOCKET-PP = smd 0.75 x 1.5: 1 3.2,16.8; 2 2.1,16.8; 3 1,16.8; 4 -0.1,16.8; 5 -1.2,16.8; 6 -2.3,16.8; 7 -3.4,16.8; 8 -4.5,16.8 | smd 1 x 1.3: CD1 -5.85,16.75 | smd 1.4 x 1: CD2 -6.425,4.5 | smd 1.5 x 1.35: GND1 -6.275,1.475; GND2 7.375,0.475
CON_CFAX_SPEC = drill 1.016 octagon: 19 1.27,50.8; +3.3V 1.27,53.34; BL_EN 1.27,-20.32; D0 1.27,7.62; D1 1.27,5.08; D2 1.27,2.54; D3 1.27,0; D4 1.27,-2.54; D5 1.27,-7.62; D6 1.27,-10.16; D7 1.27,-15.24; E_RD 1.27,10.16; GND 1.27,-22.86; RS 1.27,-17.78; RSTB 1.27,38.1; RW 1.27,12.7; TS1 1.27,40.64; TS2 1.27,43.18; TS3 1.27,45.72; TS4 1.27,48.26
MA08-1 = drill 1.016 octagon: 1 -8.89,0; 2 -6.35,0; 3 -3.81,0; 4 -1.27,0; 5 1.27,0; 6 3.81,0; 7 6.35,0; 8 8.89,0

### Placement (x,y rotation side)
B1  64.77,38.1 180 top
B2  2.54,20.48 0 top
C1  62.71,43.34 0 bottom
C2  66.83,43.34 180 bottom
C3  67.79,14.29 270 top
C4  67.95,10 270 top
C5  57.63,15.08 270 top
C6  26.04,35.48 270 bottom
C7  10.16,14.29 90 bottom
C8  52.23,14.29 90 top
C9  44.77,36.67 0 top
C10  60.96,36.83 90 bottom
C11  19.05,44.13 0 bottom
C12  19.05,48.58 0 bottom
C13  15.87,46.51 270 bottom
C14  11.59,36.51 90 bottom
C15  25.72,43.97 0 bottom
C16  7.14,36.51 90 bottom
C17  20.95,32.86 0 bottom
C18  6.03,18.57 90 bottom
D1  46.51,35.24 180 bottom
D2  82.07,10.64 270 bottom
D3  68.26,34.29 180 bottom
D4  34.13,48.26 0 top
D5  18.57,38.1 0 bottom
DRILEGEND  [DRILEGEND]  not placed on the board
H1  60.96,53.5 180 bottom
H2  62.55,53.5 180 bottom
H3  2.22,30.96 90 top
H4  28.26,49.05 90 top
MEASURE  [MEASURE]  0,0 0 top
N1  71.91,16.83 270 top
N2  71.91,13.1 90 top
N3  71.91,8.97 90 top
R1  45.88,50.17 270 bottom
R2  30.16,34.93 270 bottom
R3  33.34,34.92 270 bottom
R4  53.66,50.17 90 bottom
R5  50.32,50.17 90 bottom
R6  75.56,13.02 270 top
R7  63.66,14.29 270 top
R8  65.72,14.29 90 top
R9  75.57,8.26 270 top
R10  63.82,10 270 top
R11  79.45,6.59 90 top
R12  65.88,10 90 top
R13  64.69,11.27 270 bottom
R14  64.69,14.92 270 bottom
R15  59.05,53.5 270 bottom
R16  64.45,53.5 270 bottom
R17  21.11,46.36 180 bottom
R18  27.46,40.32 90 bottom
R19  30,40.32 90 bottom
R20  23.97,49.21 180 bottom
R21  13.18,45.72 90 bottom
R22  24.92,40.32 270 bottom
R23  9.37,38.58 90 bottom
R24  9.68,44.61 90 bottom
R25  16.35,32.86 0 bottom
R26  6.03,14.45 90 bottom
R27  10.32,22.38 90 bottom
R28  29.37,43.97 0 top
S1  82.55,52.39 0 top
U$1  not placed on the board
U$2  not placed on the board
U$3  not placed on the board
U$4  not placed on the board
V1  79.06,10.64 90 top
W1  23.5,24.77 180 bottom
X1  70.33,28.89 270 top
X2  81.6,30.32 270 top
X3  88.11,10 180 top
X4  37.31,1.11 0 top
X5  60.96,1.27 90 top
X6  14.92,53.34 180 top

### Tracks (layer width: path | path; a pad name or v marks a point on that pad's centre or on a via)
+3.3V  (via drill 0.6)
  Top 0.254: 63.66,13.02 R7.2 | 63.82,8.89 R10.2 | 43.81,36.67 | 43.81,36.67 C9.1 43.92,36.62 43.81,36.51 43.89,36.43 v43.89,34.77 | v43.74,40.8 43.74,37.39 43.81,36.67 | v47.31,20.96 v41.12,20.96 | 37.28,17.91 37.15,17.94 | 37.28,17.91 X4.4 | 37.21,17.88 37.25,17.88 37.28,17.91
  Top 0.406: 63.66,12.15 N2.5 | 63.66,12.15 63.66,13.02 | 63.81,7.94 69.85,7.94 69.93,8.02 N3.5 | 63.81,7.94 63.82,8.89 | 63.66,12.15 62.15,12.15 61.59,11.59 61.59,8.57 | 61.59,8.57 62.23,7.94 63.81,7.94 | 61.59,8.57 | 61.59,8.57 58.26,8.57 57.63,9.21 C5.+ 57.57,11.53 57.47,11.43 57.39,11.51 | v77.95,18.42 77.95,19.37 78.74,20.16 81.76,20.16 X2.20 83.98,18.89 87,21.91 87,41.43 | 57.39,11.51 56.52,11.51 54.53,13.49 52.23,13.49 | 52.23,13.49 v49.21,13.49 v37.23,13.49 v26.04,13.49 v8.41,13.49 7.14,13.49 4.29,16.35 4.29,47.47 8.89,52.07 D4.PWR 34.29,52.23 36.04,53.98 | 52.23,13.49 C8.1 | v37.23,16.27 37.21,17.88 | v26.04,16.19 26.04,35.56 25.24,36.35 v24.29,36.35 24.13,36.35 23.65,36.35 23.02,36.99 v23.02,39.37 | 36.04,53.98 v51.99,53.98 73.68,53.98 75.72,53.98 | 75.72,53.98 77.47,53.98 78.9,52.55 86.84,52.55 87.79,51.59 87.79,49.53 87,48.74 87,41.43 | 36.04,53.98 | 57.39,11.51 58.66,11.51 60.64,13.49 60.64,15.4 62.39,17.15 65.41,17.15 70.64,22.38 v74.14,22.38 | v73.18,44.29 73.68,44.79 73.68,48.44 v76.2,50.96 | 87,41.43 | 87,41.43 v87,41.75 | 75.72,53.98 | 75.72,53.98 v76.2,53.98
  Bottom 0.254: 26.04,36.35 | 26.04,36.35 C6.1 | v43.74,40.8 43.74,43 D1.21 43.76,47.73 45.25,49.22 R1.2 | 42.15,28.89 41.12,28.89 40.64,28.42 40.64,27.46 40.62,27.48 D1.64 40.61,27.34 40.64,27.31 40.64,26.67 41.59,25.72 41.59,23.34 41.12,22.86 v41.12,20.96 | D1.62 42.18,28.86 42.15,28.89 | 42.15,28.89 43.89,30.64 v43.89,34.77 | 30,41.75 30,43.82 32.7,46.51 32.7,47.78 33.18,48.26 | 33.18,48.26 | 33.18,48.26 35.4,48.26 36.04,48.9 36.04,50.96 34.92,52.07 D4.PWR | D4.PWR | v51.99,53.98 51.99,51.44 | R5.2 50.32,51.44 51.99,51.44 | R4.2 53.66,51.51 53.58,51.44 51.99,51.44 | v37.23,13.49 37.15,13.41 37.23,13.34 37.23,12.46 35.08,10.32 11.11,10.32 7.62,6.83 7.62,2.86 7.78,2.7 X5.+3.3V | D4.PWR | D5.3 22.5,38.85 v23.02,39.37 | D1.52 50.06,23.71 v47.31,20.96 | D3.11 68.26,39.85 68.58,40.16 68.9,40.48 70.48,40.48 71.44,41.43 71.44,42.7 71.91,43.18 73.18,43.18 | 71.44,39.21 72.07,39.21 72.71,39.21 73.66,39.21 | D3.13 69.88,38.92 70.17,39.21 71.44,39.21 | 71.44,39.21 | 73.18,43.18 | 73.18,43.18 73.66,42.7 73.66,39.37 | 73.66,39.37 73.66,39.21 | 73.66,33.5 73.66,30.8 72.39,29.53 64.29,29.53 63.66,30.16 63.66,33.5 | 73.66,39.37 73.66,39.21 | 73.66,39.21 73.66,33.5 | D3.3 64.78,33.49 64.77,33.5 63.66,33.5 | 73.66,33.5 | D3.19 73.65,33.49 73.66,33.5 | C10.1 60.96,34.45 61.91,33.5 63.5,33.5 63.66,33.5
  Bottom 0.406: X2.20 83.66,18.89 | v74.14,22.38 74.14,22.23 v77.95,18.42 | v49.21,13.49 49.21,18.1 47.31,20 v47.31,20.96 | v37.23,13.49 v37.23,16.27 | 30,41.75 | 30,41.75 R19.2 | R18.2 29.98,41.72 30,41.75 | C7.1 10.16,13.49 v8.41,13.49 v8.41,13.5 R26.1 | v26.04,13.49 v26.04,16.19 | 73.18,43.18 | v73.18,44.29 73.18,43.18 | v87,41.75 X2.4 | v76.2,50.96 76.2,53.82 v76.2,53.98 | v24.29,36.35 26.04,36.35 24.13,36.35 v24.29,36.35
/POK
  Top 0.254: N2.3 73.21,14 73.18,13.97 73.11,14.05 | R6.1 75.54,14.42 75.09,13.97 73.34,13.97 73.21,14.1 | N1.3 71.59,15.88 71.91,15.56 | 73.21,14.1 73.18,14.13 | N2.3 73.21,14.1 | 73.18,14.13 73.1,14.05 | 71.91,15.56 | 71.91,15.56 72.39,15.08 72.87,15.08 73.18,14.76 73.18,14.13 | N2.3 73.26,14.05 73.18,14.13
BL_EN
  Bottom 0.254: D1.41 54.29,34.85 55.8,34.85 62.87,27.78 | X5.BL_EN 81.28,4.13 79.22,6.19 71.75,6.19 69.69,8.26 64.14,8.26 62.87,9.53 62.87,27.62 62.87,27.78 | 62.87,27.78
BT_RX  (via drill 0.6)
  Top 0.254: v41.27,33.5 41.27,43.02 39.85,44.45 35.56,44.45 D4.RX-I | D4.RX-I | D4.RX-I
  Bottom 0.254: D1.3 40.12,30.91 41.27,32.07 v41.27,33.5
BT_TX  (via drill 0.6)
  Top 0.254: v42.55,34.13 42.55,43.97 39.53,46.99 35.4,46.99 | 35.4,46.99 | 35.4,46.99 D4.TX-O
  Bottom 0.254: D1.2 41.08,30.13 42.55,31.59 v42.55,34.13
CAP_CHG
  Bottom 0.254: D5.6 27.1,37.35 28.1,36.35 30.16,36.35 | 30.16,36.35 R2.1 | 30.16,36.35 31.43,36.35 31.75,36.67 31.75,39.53 32.23,40.01 32.23,42.07 33.34,43.18 34.92,43.18 37.78,40.32 38.66,40.32 38.69,40.36 D1.15
CAP_DRDY  (via drill 0.6)
  Top 0.254: v35.64,36.43 34.77,37.31 29.21,37.31 25.72,40.8 17.62,40.8 16.03,39.21 14.29,39.21 13.81,39.53 v12.7,39.53 | v36.83,39.69 37.78,38.74 37.78,36.67 37.39,36.27 35.8,36.27 v35.64,36.43 | v35.64,36.43
  Bottom 0.254: v35.64,36.43 35.56,36.43 35.56,36.42 33.41,36.42 33.34,36.35 R3.1 33.34,36.2 | D1.14 36.94,39.57 v36.83,39.69 | D5.21 13.88,38.35 v12.7,39.53 | v12.7,39.53
CAP_MISO  (via drill 0.6)
  Top 0.254: v12.7,42.7 | v12.7,42.7 13.34,43.34 26.43,43.34 30.56,39.21 31.59,39.21 32.86,40.48 34.13,40.48 v34.29,40.32
  Bottom 0.254: D5.26 17.32,40.94 15.56,42.7 v12.7,42.7 | D1.13 35.83,38.79 v34.29,40.32
CAP_MOSI  (via drill 0.6)
  Top 0.254: v14.13,41.75 15.08,42.7 26.19,42.7 30.16,38.74 32.54,38.74 v33.34,39.53
  Bottom 0.254: D5.25 16.82,40.64 15.56,41.91 14.29,41.91 v14.13,41.75 | v33.34,39.53 34.61,38.26 | 34.61,38.26 | 34.61,38.26 34.77,38.1 37.15,38.1 37.25,38 D1.12
CAP_RST
  Bottom 0.254: D5.2 21.73,39.35 22.7,40.32 30,40.32 | R19.1 29.84,38.74 30,38.74 30,40.32 | 30,40.32 31.11,40.32 31.59,40.8 31.59,44.61 32.54,45.56 32.7,45.72 38.26,45.72 39.85,44.13 40.96,44.13 41.43,43.66 41.43,43.18 41.4,43.14 D1.18
CAP_SCK  (via drill 0.6)
  Top 0.254: v12.7,41.43 | v12.7,41.43 13.02,41.12 13.49,41.12 14.76,39.85 15.72,39.85 17.3,41.43 25.88,41.43 29.53,37.78 36.12,37.78 v36.67,37.23
  Bottom 0.254: D5.23 15.26,39.35 13.49,41.12 13.02,41.12 v12.7,41.43 | v12.7,41.43 | D1.11 38.73,37.23 v36.67,37.23
CAP_SS  (via drill 0.6)
  Top 0.254: v15.24,40.96 | v15.24,40.96 16.35,42.07 26.04,42.07 27.15,40.96 | 27.15,40.96 | 27.15,40.96 29.84,38.26 34.13,38.26 36.99,41.12 39.37,41.12 40.32,40.16 v40.32,38.26
  Bottom 0.254: D5.24 15.87,39.85 15.24,40.48 v15.24,40.96 | v40.32,38.26 40.32,36.91 39.85,36.43 38.81,36.43 38.8,36.42 D1.10
D0
  Bottom 0.254: D1.51 50.84,26.15 55.88,21.11 55.88,6.67 53.34,4.13 X5.D0
D1
  Bottom 0.254: D1.50 51.63,26.31 56.52,21.43 56.52,5.72 55.88,5.08 X5.D1
D2
  Bottom 0.254: D1.49 52.41,27.48 52.39,27.46 52.39,26.51 57.15,21.75 57.15,5.72 58.42,4.45 X5.D2
D3
  Bottom 0.254: D1.48 55.59,29.34 58.42,26.51 59.05,25.88 59.05,7.62 60.96,5.72 X5.D3
D4
  Bottom 0.254: D1.47 55.76,30.13 59.69,26.19 | X5.D4 63.5,3.65 63.5,4.13 59.85,7.78 59.69,7.94 59.69,26.19 | 59.69,26.19
D5
  Bottom 0.254: D1.46 55.92,30.91 60.33,26.51 60.33,8.26 62.87,5.72 67.79,5.72 68.58,4.92 X5.D5
D6
  Bottom 0.254: D1.45 56.09,31.7 60.96,26.83 60.96,8.57 63.18,6.35 68.1,6.35 70.01,4.45 71.12,3.33 X5.D6
D7
  Bottom 0.254: D1.44 56.26,32.49 61.59,27.15 61.59,8.89 63.5,6.99 68.58,6.99 68.74,6.99 70.96,4.76 74.77,4.76 75.56,3.97 | 75.56,3.97 76.2,3.33 X5.D7 | 75.56,3.97
D+  (via drill 0.6)
  Top 0.254: X3.2 82.56,9.2 82.23,9.53 | 82.23,9.53 | 82.23,9.53 81.76,10 81.76,14.13 80.96,14.92 v78.42,14.92
  Bottom 0.254: D2.5 82.57,15.06 82.07,15.56 79.06,15.56 v78.42,14.92
D-  (via drill 0.6)
  Top 0.254: X3.3 82.87,10 82.39,10.48 82.39,14.45 80.8,16.03 v77.63,16.03
  Bottom 0.254: v77.63,16.03 | v77.63,16.03 77.15,15.56 77.15,14.45 77.63,13.97 79.06,13.97 80.01,14.92 81.76,14.92 82.07,14.61 D2.4
E_RD  (via drill 0.6)
  Top 0.254: v55.24,26.67 56.36,27.78 v60.33,31.75 | X5.E_RD 50.8,4.29 52.55,6.03 58.26,6.03 v58.58,5.87
  Bottom 0.254: v60.33,31.75 | v60.33,31.75 57.78,34.29 | v55.24,26.67 | v55.24,26.67 54.61,26.04 54.61,25.4 55.56,24.45 56.36,24.45 57.78,23.02 57.78,6.67 v58.58,5.87 | 57.78,34.29 | D1.40 56.44,35.64 57.78,34.29
ENLIPO1
  Top 0.254: 76.04,9.05 | R9.1 76.04,9.05 | R9.1 75.56,9.53 75.17,9.92 N3.3 | V1.3 77.95,10.64 77.15,9.84 75.56,9.84 R9.1
GND  (via drill 0.6)
  Top 0.254: 67.79,13.49 C3.2 | 68.42,13.1 68.26,13.26 68.02,13.26 67.79,13.49 | 67.79,13.49 | 67.79,13.49 67.63,13.34 | R8.1 | 67.94,9.21 C4.2 | 67.94,9.21 68.18,8.97 | 67.94,9.05 67.94,9.21 | 66.04,9.05 65.88,9.21 R12.1 67.94,9.05 | 67.94,9.05 | 67.94,9.05 68.02,8.97 71.91,8.97 | 80.17,13.1 80.17,13.18 80.16,13.17 V1.2 | v45.4,40.8 45.4,36.67 45.46,36.62 C9.2 45.56,36.67 | v46.35,22.07 v42.07,22.07 | 45.56,36.67 | v45.56,33.5 45.56,36.67 | 77.95,13.1 v77.95,13.02 | D4.GND | 34.13,49.37 D4.GND | 61.75,52.39 v61.75,51.12
  Top 0.406: 71.91,13.1 71.68,13.1 | 71.68,13.1 68.42,13.1 | 71.91,13.1 N2.2 77.95,13.1 80.17,13.1 | 67.63,13.34 R8.1 | 68.18,8.97 N3.2 | 67.94,9.05 66.04,9.05 | 71.91,8.97 71.91,13.1 | 69.69,16.83 70.48,16.83 N1.2 69.69,16.83 | 69.69,16.83 69.22,16.35 69.22,15.64 69.85,15 71.2,15 71.68,14.53 71.68,13.1 | 84.93,44.29 X2.2 | 84.93,44.29 84.93,35.08 83.98,34.13 X2.10 X2.12 X2.11 | 52.23,15.08 v47.94,15.08 37.07,15.08 | 52.23,15.08 C8.2 | 52.23,15.08 54.93,15.08 57.15,15.08 57.63,15.56 57.63,18.57 | X4.6 35.01,15.08 37.07,15.08 | v24.29,15.08 v8.41,15.08 7.3,15.08 5.56,16.83 v5.56,23.02 v5.56,27.46 v5.56,46.83 | v24.29,15.08 37.07,15.08 | v5.56,46.83 | v5.56,46.83 | v5.56,46.83 10,51.28 32.23,51.28 34.13,49.37 37.15,52.39 61.75,52.39 77.15,52.39 79.3,50.24 | v24.29,15.08 v24.29,34.77 19.53,34.77 18.49,35.8 12.78,35.8 11.59,36.99 11.59,40.32 v11.59,40.48 | 79.3,50.24 79.38,50.17 | 79.38,50.17 | 79.38,50.17 84.93,50.17 | 84.93,50.17 84.93,44.29 | 80.25,29.13 80.33,29.05 77.63,26.35 77.63,22.7 75.56,20.64 71.28,20.64 70.33,19.69 70.17,19.69 69.22,18.73 69.22,17.3 69.69,16.83 | 57.63,18.57 | 57.63,18.57 C5.- 57.63,18.57 | 57.63,18.57 | v24.29,12.38 24.29,5.87 27.62,2.54 30.8,2.54 30.84,2.59 X4.GND1 31,2.59 30.96,2.54 43.66,2.54 44.61,1.59 X4.GND2 | 57.63,18.57 | 57.63,18.57 v64.14,18.57 65.41,18.57 70.17,23.34 70.17,23.5 70.17,26.83 70.33,26.99 X1.P2 | v5.56,46.83 | v5.56,46.83 | v5.56,46.83 | R11.1 80.22,5.19 80.22,4.39 80.64,3.97 82.55,3.97 83.82,2.7 | X5.GND 83.82,2.7 | 83.98,2.54 X5.GND | 85.09,5.55 85.09,5.56 85.09,5.55 | X3.M3 85.09,5.55 | X3.M3 X3.M2 91.12,5.56 90.89,5.79 90.89,14.45 | X3.M3 85.09,5.55 | 85.09,14.45
  Top 0.406: 85.09,14.45 X3.M4 | 88.11,14.45 85.09,14.45 | 90.89,14.45 88.11,14.45 | 90.89,14.45 X3.M1 | X3.5 86.98,11.6 87.47,11.11 88.44,11.13 89.22,11.91 89.22,12.86 88.11,13.97 88.11,14.45 | 90.89,14.45 90.89,16.1 88.11,18.89 v88.11,34.13 | S1.4 85.76,50.13 85.72,50.17 84.93,50.17 | 79.3,50.24 79.22,50.17 79.25,50.13 S1.3 | 79.3,50.24 | X5.GND 83.82,2.7 | 83.98,2.54 X5.GND | X3.M3 85.21,3.77 83.98,2.54
  Bottom 0.254: 26.04,34.77 C6.2 | 30.16,33.5 | 30.16,33.5 R2.2 | R3.2 33.34,33.5 33.31,33.53 | 66.2,43.34 | 66.2,43.34 C2.1 | 66.2,43.34 | D1.22 44.55,41.66 v45.4,40.8 | D1.63 41.4,26.87 42.23,26.04 42.23,22.23 v42.07,22.07 | v46.35,22.07 46.04,22.38 46.04,25.88 46.51,26.35 48.82,26.35 49.29,26.83 49.29,27.38 49.27,27.41 D1.53 49.27,29.27 52.39,32.39 52.39,36.99 51.75,37.62 50.8,37.62 46.67,33.5 v45.56,33.5 | 64.77,43.34 | H3.K 0.95,30.96 0.95,28.58 2.06,27.46 v2.22,27.46 v5.56,27.46 | C15.1 28.57,43.97 31.27,46.67 31.27,47.15 32.38,48.26 32.38,48.9 | 32.38,48.9 | H4.K 31.59,50.32 32.38,49.53 | D5.22 14.65,38.85 14.61,38.89 13.02,40.48 v11.59,40.48 | 64.77,43.34 | v64.77,39.53 | X6.8 | X6.8 7.3,54.61 13.65,54.61 | X6.5 | 13.65,54.61 X6.5 | X6.1 | X6.1 22.54,54.61 13.65,54.61 | D2.3 81.57,13.84 81.28,14.13 80.01,14.13 78.9,13.02 v77.95,13.02 | D4.GND 32.38,49.53 | 32.38,48.9 | 32.38,49.53 32.38,48.9 | H1.C 61.02,52.45 61.12,52.55 61.22,52.45 61.76,52.45 | 61.76,52.45 H2.C | 61.76,52.45 v61.76,51.12 v61.75,51.12 | D3.17 71.6,35.09 71.6,35.08 71.59,35.09 68.26,35.09 | 68.26,35.09 D3.5 64.92,35.09 64.93,35.08 63.18,35.08 62.71,35.56 62.71,37.62 62.63,37.7 | 68.26,35.09 68.26,35.24 | 68.26,35.24 D3.0 | 68.26,35.24 | D3.2 68.25,32.69 68.26,32.7 D3.0 | D3.0 | C10.2 62.17,37.68 62.63,37.7 | v64.77,39.53 63.34,39.53 62.71,38.89 62.71,37.78 62.63,37.7
  Bottom 0.406: C6.2 27.12,34.63 28.26,33.5 30.16,33.5 | R2.2 33.31,33.53 | 66.2,43.34 C1.1 64.77,43.34 v64.77,39.53 | v46.35,22.07 | v46.35,22.07 46.04,21.75 46.04,19.69 47.94,17.78 v47.94,15.08 | C7.2 10.16,15.08 8.57,15.08 | C18.2 7.72,19.42 8.41,18.73 8.41,15.24 8.57,15.08 | v8.41,15.08 8.57,15.08 | v5.56,23.02 B2.GND | v24.29,34.77 26.04,34.77 | R14.1 64.77,15.95 64.69,16.03 64.69,18.02 v64.14,18.57 | v24.29,15.08 v24.29,12.38 | v5.56,46.83 5.56,52.86 X6.8 | X2.10 | X2.10 v88.11,34.13
  other vias: 8.89,4.29 11.43,4.29 13.97,4.29 16.51,4.29 19.05,4.29 21.59,4.29 33.02,4.29 37.31,4.29 41.91,4.29 2.54,5.56 2.54,9.05 2.54,12.22 2.54,15.4 5.4,9.05 11.91,9.05 2.54,36.04 2.54,38.74 2.54,41.43 2.54,44.13 2.54,47.15 2.54,49.85 9.05,32.23 9.05,29.69 26.67,53.34 29.84,53.34 40.8,52.07 40.8,49.53 48.26,9.05 53.02,9.05 52.07,18.1 52.07,20.96 47.62,23.34 51.59,23.34 54.13,27.78 64.45,27.94 80.33,31.75 85.57,31.75 90.01,31.75 90.01,27.78 90.01,25.08 90.01,22.7 90.01,20.16 90.01,35.4 90.01,37.94 90.01,40.48 90.01,43.02 90.01,47.15 90.01,50.48 83.03,47.15 54.13,42.7 66.04,2.54 73.66,2.54 52.07,3.81 49.53,3.81 54.61,3.81 57.15,3.81 90.96,10 67.31,27.94
  pour Bottom: 0,0 92.55,0 92.55,55.88 0,55.88
  pour Top: 0,0 92.55,0 92.55,55.88 0,55.88
IR_RX  (via drill 0.6)
  Top 0.254: 32.23,20.32 34.45,22.54 34.45,23.65 34.45,27.62 39.37,32.54 v40.32,32.54 | 32.23,20.32 | v31.59,19.69 32.23,20.32
  Bottom 0.254: v31.59,19.69 29.53,17.62 25.24,17.62 23.5,15.88 12.7,15.88 9.84,18.73 6.83,21.75 6.83,23.34 4.6,25.56 B2.OUT | v40.32,32.54 39.61,33.26 38.73,33.26 D1.6
IR_TX  (via drill 0.6)
  Top 0.254: 39.77,34.05 v40.32,34.61 39.37,33.66 39.37,33.34 33.81,27.78 33.81,22.86 31.91,20.96 | v6.51,25.24 6.51,46.2 10.79,50.48 26.04,50.48 27.15,49.37 27.15,44.61 28.26,43.97 R28.1 | v30.16,19.69 | v30.16,19.69 31.11,20.64 31.59,20.64 31.91,20.96 | 31.91,20.96
  Bottom 0.254: D1.7 39.78,34.06 v40.32,34.61 | v30.16,19.69 28.89,18.42 25.08,18.42 23.34,16.67 14.29,16.67 11.27,19.69 10.32,20.64 R27.1 | R27.1 | R27.1 8.25,21.43 7.46,22.23 7.46,24.29 v6.51,25.24
LED1  (via drill 0.6)
  Top 0.254: v59.37,46.67 65.09,46.67 66.67,48.26 v66.67,51.12
  Bottom 0.254: D1.38 55.63,37.21 56.36,37.94 56.36,43.66 v59.37,46.67 | v66.67,51.12 64.93,51.12 64.45,51.59 R16.2 | R16.2 | R16.2
LED2  (via drill 0.6)
  Top 0.254: v57.63,46.67 57.47,46.83 56.67,47.63 v56.67,51.12
  Bottom 0.254: D1.37 55.3,38 55.72,38.42 55.72,44.77 56.83,45.88 v57.63,46.67 | v56.67,51.12 58.58,51.12 59.05,51.59 59.05,52.39 | 59.05,52.39 | 59.05,52.39 R15.2
N$1
  Bottom 0.254: R16.1 64.3,54.45 64.14,54.61 64.07,54.55 H2.A
N$2
  Bottom 0.254: R27.2 10.32,24.77 5.4,29.69 H3.A
N$3
  Top 0.254: R28.2 30.32,44.13 30.8,44.61 30.8,46.83 29.84,47.78 H4.A
N$4
  Bottom 0.254: D5.4 23.27,38.35 23.81,38.89 | 23.81,38.89 R22.2 | R18.1 23.84,38.92 23.81,38.89
N$5  (via drill 0.6)
  Top 0.406: D4.RTS-O 33.34,41.91 32.38,42.86 32.38,47.63 33.02,48.26 36.51,48.26 37.47,49.21 v37.47,49.53
  Bottom 0.406: v37.47,49.53 37.47,53.02 35.88,54.61 D4.CTS-I | D4.CTS-I
N$6
  Bottom 0.254: 60.96,54.61 | 60.96,54.61 H1.A | R15.1 60.8,54.45 60.96,54.61
N$7
  Bottom 0.254: R25.1 18.41,32.86 18.89,32.86 | D5.12 18.82,33.41 18.82,32.93 18.89,32.86 | C17.2 19.84,32.86 18.89,32.86
N$8
  Bottom 0.254: D5.29 18.82,42.22 18.26,42.78 18.26,43.5 | 18.26,43.5 | R17.1 18.57,46.36 18.26,46.04 18.26,43.5 | 18.26,43.5 C11.2
N$9
  Bottom 0.254: D5.30 19.32,42.18 19.84,42.7 19.84,43.5 C11.1
N$10
  Bottom 0.254: D5.31 19.82,41.41 21.11,42.7 21.11,47.94 20.48,48.58 C12.1 19.84,48.58
N$11
  Bottom 0.254: D5.28 18.32,41.45 17.46,42.31 | 17.46,42.31 | 17.46,42.31 16.99,42.78 16.99,47.94 17.62,48.58 C12.2 18.2,48.68 18.26,48.74 18.26,49.37 18.73,49.85 22.07,49.85 22.57,49.34 R20.1
N$12  (via drill 0.6)
  Top 0.254: v15.88,48.9 20.8,48.9 22.07,47.63 v22.07,44.29 | v22.07,44.29
  Bottom 0.254: D5.32 20.32,41.12 21.59,42.39 | 21.59,42.39 | 21.59,42.39 22.07,42.86 v22.07,44.29 | v15.88,48.9 C13.1 | v15.88,48.9
N$13
  Bottom 0.254: D5.27 17.82,41.15 16.03,42.94 | 16.03,45.72 | 16.03,42.94 16.03,45.72 | 16.03,42.94 16.03,44.45 14.13,44.45 13.78,44.48 R21.1 | 16.03,45.72 15.88,45.72 15.82,45.82 C13.2
N$14
  Bottom 0.254: D5.17 13.01,36.35 12.54,35.88 11.59,35.88 | 11.59,35.88 | C14.1 11.59,35.88
N$15
  Bottom 0.254: D5.18 13,36.85 12.54,37.31 11.59,37.31 | 11.59,37.31 | 11.59,37.31 C14.2 9.47,37.36 9.37,37.62 | R23.1 9.37,37.62 | 9.37,37.62 9.21,37.47
N$16
  Bottom 0.254: D5.7 22.52,36.85 22.86,36.51 22.86,33.34 22.38,32.86 21.75,32.86 C17.1
N$17
  Bottom 0.254: C16.1 7.2,35.66 7.3,35.24 8.1,34.45 15.88,34.45 16.83,35.4 16.82,35.41 D5.16
N$18
  Bottom 0.254: D5.19 13.77,37.35 12.54,38.58 7.14,38.58 | 7.14,37.31 7.14,38.58 | 7.14,37.31 | C16.2 7.14,37.31 | 7.14,37.31 6.82,37.31 | R24.1 9.68,43.02 7.14,40.48 7.14,38.58
N$19
  Bottom 0.254: W1.P$1 11.91,24.77 11.27,25.4 11.27,31.43 12.54,32.7 | 12.54,32.7 | 12.54,32.7 12.7,32.86 14.76,32.86 R25.2
N$21
  Bottom 0.254: D5.1 21.28,39.85 23.18,41.75 23.65,41.75 | 23.65,41.75 | 23.65,41.75 R22.1 24.92,43.97 24.61,43.97 C15.2
N$29
  Bottom 0.254: R17.2 25.72,46.36 27.15,47.78 27.15,50.96 27.15,51.44 26.35,52.23 21.75,52.23 21.27,52.71 X6.2
N$30
  Bottom 0.254: R20.2 25.4,49.37 25.4,51.12 | 25.4,51.12 | X6.3 18.73,52.07 19.37,51.44 25.08,51.44 25.4,51.12
N$31
  Bottom 0.254: R21.2 13.18,48.9 16.19,51.91 X6.4
N$32
  Bottom 0.254: R23.2 9.37,41.12 10,41.75 11.11,41.75 11.59,42.23 11.59,48.58 | X6.6 11.11,49.53 11.59,49.05 11.59,48.58 | 11.59,48.58
N$33
  Bottom 0.254: 9.68,46.2 | R24.2 9.68,46.2 | 9.68,46.2 9.68,48.26 8.57,49.37 X6.7
N$48
  Top 0.254: R10.1 R12.2 66.04,10.8 66.1,10.85 C4.1 68.05,10.85 68.1,10.8 69.06,10.8 69.93,9.92 N3.4
N$50
  Top 0.254: R8.2 65.83,15.14 | 65.83,15.14 C3.1 68.52,15.14 69.61,14.05 N2.4 | R7.1 | R7.1 | 65.83,15.14 63.76,15.14 R7.1
PD6
  Bottom 0.254: D1.31 51.63,43.85 52.07,44.29 56.36,48.58 74.45,48.58 76.83,46.2 76.83,26.04 78.9,23.97 X2.15
PD7
  Bottom 0.254: D1.32 52.42,43.21 52.7,43.5 | 52.7,43.5 | 52.7,43.5 52.86,43.66 56.99,47.78 74.14,47.78 76.04,45.88 76.04,25.56 78.9,22.7 81.6,22.7 X2.16
RESET  (via drill 0.6)
  Top 0.254: v47.78,50.96 47.78,48.74 50.96,45.56 68.74,45.56 70.64,43.66 70.64,41.12 72.07,39.69 75.88,39.69 77.31,41.12 77.31,43.97 79.85,46.51 80.96,46.51 v81.6,45.88 | v81.6,45.88 | v47.78,54.93 78.26,54.93 78.54,54.65 S1.1 85.69,54.65 85.72,54.61 85.76,54.65 S1.2
  Bottom 0.254: X2.6 81.6,40.48 v81.6,45.88 | D1.20 43,43 43.02,43.02 43.02,49.53 44.45,50.96 45.88,50.96 46.99,50.96 v47.78,50.96 v47.78,54.93 | v81.6,45.88 | v81.6,45.88
  Bottom 0.406: 45.88,50.96 R1.1 | R1.1
RS
  Bottom 0.254: X5.RS 78.74,3.97 77.15,5.56 71.28,5.56 69.22,7.62 63.82,7.62 62.23,9.21 62.23,27.46 55.63,34.06 D1.42
RSTB  (via drill 0.6)
  Top 0.254: v50.48,29.21 49.53,28.26 49.37,28.26 49.21,28.26 39.05,28.26 37.62,26.83 37.62,22.7 40.32,20 43.97,20 45.4,18.57 | 45.4,18.57 | v46.2,17.78 45.4,18.57
  Bottom 0.254: D1.43 53.44,33.27 53.02,32.86 53.02,31.75 v50.48,29.21 | v46.2,17.78 46.2,12.7 40.64,7.14 28.1,7.14 24.45,7.14 22.86,5.56 X5.RSTB
RW  (via drill 0.6)
  Top 0.254: v56.36,25.56 v61.44,30.64 | X5.RW 48.26,4.29 50.8,6.83 | 50.8,6.83 | 50.8,6.83 51.28,7.3 59.21,7.3 59.69,6.83 v59.69,5.08
  Bottom 0.254: v61.44,30.64 61.44,32.07 58.74,34.77 57.08,36.42 D1.39 | v56.36,25.56 | v56.36,25.56 58.42,23.5 58.42,7.3 59.69,6.03 59.69,5.24 | 59.69,5.24 | v59.69,5.08 59.69,5.24
SCL  (via drill 0.6)
  Top 0.254: v72.55,50.96 72.55,47.15 72.55,45.56 71.44,44.45 71.44,43.18 v72.55,42.07
  Bottom 0.254: D1.25 46.91,43.89 47.47,44.45 47.47,47.31 48.42,48.26 50.32,48.26 | 50.32,48.26 R5.1 | 50.32,48.26 50.32,48.74 51.75,50.17 69.69,50.17 70.48,50.96 v72.55,50.96 | v72.55,50.96 74.3,50.96 78.74,46.51 78.74,27.46 79.69,26.51 X2.13 | D3.12 69.07,39.39 69.53,39.85 71.12,39.85 72.55,41.28 | 72.55,41.28 | v72.55,42.07 72.55,41.28 | v72.55,50.96
SD_CS  (via drill 0.6)
  Top 0.254: v50.01,40.01 50.01,31.27 47.62,28.89 38.89,28.89 36.99,26.99 36.99,23.5 | X4.2 39.41,20.04 36.99,22.46 36.99,23.5 | 36.99,23.5
  Bottom 0.254: D1.29 50.06,40.06 v50.01,40.01
SD_DI  (via drill 0.6)
  Top 0.254: v48.58,40.01 49.37,39.21 49.37,31.43 47.47,29.53 38.73,29.53 36.35,27.15 36.35,23.5 36.35,22.23 38.31,20.29 X4.3
  Bottom 0.254: v48.58,40.01 | v48.58,40.01 49.29,40.72 49.29,42.78 49.21,42.86 49.27,42.92 D1.28
SD_DO  (via drill 0.6)
  Top 0.254: v46.67,40.01 46.67,39.53 48.1,38.1 48.1,31.91 46.99,30.8 38.42,30.8 35.08,27.46 35.08,23.5 35.08,22.23 33.91,21.05 X4.7
  Bottom 0.254: v46.67,40.01 | v46.67,40.01 48.42,41.75 48.42,42.86 48.48,42.93 D1.27
SD_SCK  (via drill 0.6)
  Top 0.254: v51.44,40.01 50.16,41.28 48.1,41.28 47.62,40.8 47.62,39.53 48.74,38.42 48.74,31.59 47.31,30.16 38.58,30.16 35.72,27.31 35.72,23.5 35.72,21.91 36.11,21.5 X4.5
  Bottom 0.254: v51.44,40.01 50.88,40.56 50.84,40.61 D1.30
SDA  (via drill 0.6)
  Top 0.254: v71.28,49.69 71.28,47.15 71.28,45.88 v70.64,45.24
  Bottom 0.254: D1.26 47.7,43.73 48.26,44.29 48.26,46.36 48.9,46.99 52.86,46.99 53.66,47.78 53.66,48.26 | R4.1 53.66,48.42 53.66,48.26 | 53.66,48.26 53.66,48.58 54.45,49.37 70.17,49.37 70.48,49.69 | 70.48,49.69 v71.28,49.69 | v71.28,49.69 74.45,49.69 77.79,46.36 77.79,26.35 78.9,25.24 81.44,25.24 X2.14 | D3.10 67.45,40.47 68.1,41.12 69.85,41.12 70.64,41.91 v70.64,45.24 | 70.48,49.69 v71.28,49.69
TCK  (via drill 0.6)
  Top 0.254: v51.28,36.67 52.07,36.67 52.55,36.2 77.15,36.2 78.11,37.15 78.11,43.5 78.9,44.29 X2.1
  Bottom 0.254: D1.57 46.12,31.52 v51.28,36.67
TDI  (via drill 0.6)
  Top 0.254: v51.28,32.86 78.58,32.86 | 78.58,32.86 | 78.58,32.86 79.85,34.13 X2.9
  Bottom 0.254: D1.54 48.48,30.07 v51.28,32.86
TDO  (via drill 0.6)
  Top 0.254: v51.28,34.13 78.11,34.13 78.58,34.61 79.06,35.08 79.38,35.4 81.12,35.4 81.6,36.04 81.6,40.48 X2.3
  Bottom 0.254: D1.55 47.7,30.55 v51.28,34.13
TMS  (via drill 0.6)
  Top 0.254: v51.28,35.4 78.11,35.4 78.74,36.04 78.74,38.26 79.69,39.21 X2.5
  Bottom 0.254: D1.56 46.91,31.03 v51.28,35.4
TS1
  Bottom 0.254: 45.24,12.7 40.32,7.78 26.19,7.78 22.54,7.78 20.32,5.56 20.32,3.02 X5.TS1 | 45.24,12.7 | D1.58 45.33,12.79 45.24,12.7
TS2
  Bottom 0.254: 44.45,12.86 40.01,8.41 23.5,8.41 20.64,8.41 17.78,5.56 X5.TS2 | 44.45,12.86 44.53,12.94 | 44.45,12.86 | D1.59 44.55,12.95 44.45,12.86
TS3
  Bottom 0.254: D1.60 43.76,13.12 39.69,9.05 20.64,9.05 18.73,9.05 15.24,5.56 15.24,2.86 X5.TS3
TS4
  Bottom 0.254: D1.61 42.97,13.28 39.37,9.68 17.94,9.68 16.83,9.68 12.7,5.56 12.7,2.38 X5.TS4
USB_PWR  (via drill 0.6)
  Top 0.254: v39.53,25.88 40.96,25.88 41.59,25.24 54.29,25.24 56.04,23.5 65.88,23.5 67.15,22.23 v67.15,21.91
  Bottom 0.254: D1.4 38.75,31.61 38.73,31.59 38.66,31.67 37.7,31.67 37.15,31.12 37.15,26.83 38.1,25.88 v39.53,25.88 | v67.15,21.91 67.15,22.7 66.36,23.5 65.56,23.5 64.14,22.07 64.14,20.16 66.52,17.78 66.52,13.81 65.88,13.18 64.69,13.18
  Bottom 0.406: 64.69,12.38 R13.1 | 64.69,12.38 64.69,13.18 R14.2 | 64.69,12.38
USB_RX  (via drill 0.6)
  Top 0.254: v38.73,24.77 53.98,24.77 55.88,22.86 65.09,22.86 v65.72,22.23
  Bottom 0.254: D1.8 37.55,34.85 36.35,33.66 36.35,26.04 37.62,24.77 v38.73,24.77 | v65.72,22.23 64.77,21.27 64.77,20.48 67.31,17.94 67.31,12.54 72.23,7.62 75.72,7.62 78.74,10.64 D2.25
USB_TX  (via drill 0.6)
  Top 0.254: v39.53,23.65 40.96,23.65 41.59,24.29 53.66,24.29 55.72,22.23 64.29,22.23 | 64.29,22.23 | 64.29,22.23 65.56,20.96 v65.88,20.96
  Bottom 0.254: D1.9 37.06,35.64 35.56,34.13 35.56,25.08 36.99,23.65 v39.53,23.65 | v65.88,20.96 65.88,20.32 68.1,18.1 68.1,12.7 72.39,8.41 75.09,8.41 75.56,8.41 78.29,11.14 D2.26
VCC
  Bottom 0.406: R26.2 6.03,17.78 C18.1 6.03,17.62 5.87,17.78 3.49,17.78 2.54,18.73 B2.VCC
VDC  (via drill 0.6)
  Top 0.254: 79.38,7.62 79.45,7.7 R11.2 | V1.1
  Top 0.406: N1.4 74.46,15.88 74.45,15.88 75.56,16.99 79.38,16.99 80.33,17.94 X2.19
  Top 0.508: v82.39,6.83 81.76,7.46 79.85,7.46 79.38,7.62 | v82.39,6.83 | v82.39,6.83 | R11.2 79.45,8.97 V1.1
  Bottom 0.406: X2.19 80.33,17.94 80.96,17.3 85.72,17.3 87,16.03 87,7.46 86.36,6.83 v82.39,6.83 | v82.39,6.83
VLIPO  (via drill 0.6)
  Top 0.254: 75.56,12.07 | 75.56,12.07 R6.2 | 75.56,12.07 75.48,12.15 N2.1 73.21,10.98 v73.18,11.03
  Top 0.406: X1.P1 71.28,28.89 | X1.P1 | v73.34,28.89 X1.P1 | N1.5 74.77,17.78 v75.88,18.89
  Bottom 0.406: v73.18,11.03 73.18,16.83 71.6,18.42 71.6,20.64 | 71.6,20.64 71.6,22.86 73.34,24.61 v73.34,28.89 | 75.09,19.69 v75.88,18.89 | 75.09,19.69 | 75.09,19.69 74.14,20.64 71.6,20.64
VUSB  (via drill 0.6)
  Top 0.254: 73.74,8.02 N3.1 | N1.1 70.17,17.78 | 76.04,6.99 R9.2 | 76.04,6.99 | 85.25,8.41 87,8.41 87.47,8.89 87.47,9.53 v88.11,10
  Top 0.406: 73.74,8.02 74.77,6.99 76.04,6.99 | N1.1 71.28,17.78 71.75,18.26 72.71,19.21 v73.18,19.21 | 76.04,6.99 | 76.04,6.99 76.36,6.67 80.96,6.67 82.23,5.4 v82.39,5.4 | 85.25,8.41 85.24,8.4 X3.1 | v87.31,17.3 86.2,17.3 v85.25,16.35 | v85.25,16.35
  Bottom 0.254: R13.2 64.69,9.6 65.41,8.89 70.01,8.89 72.07,6.83 80.49,6.83 81.92,5.4 v82.39,5.4 | D2.7 83.57,16.28 83.5,16.35 | D2.8 85.16,12.14 86.04,13.02 86.04,13.49 86.04,15.56 v85.25,16.35 85.88,15.72
  Bottom 0.406: v73.18,19.21 | v73.18,19.21 75.03,17.41 75.25,17.3 79.85,17.3 80.8,16.35 | 80.8,16.35 80.01,17.15 | v85.25,16.35 83.5,16.35 80.8,16.35 | v87.31,17.3 88.11,16.51 88.11,13.97 89.22,12.86 89.22,11.91 88.11,10.8 v88.11,10 88.11,9.68 | v82.39,5.4 87.47,5.4 89.22,7.14 89.22,7.94 88.11,9.05 88.11,9.68 | 88.11,9.68 | v82.39,5.4 | v82.39,5.4 | v85.25,16.35 | v85.25,16.35
XINT1  (via drill 0.6)
  Top 0.254: v52.55,41.28 56.52,41.28 v57.39,42.15
  Bottom 0.254: D1.17 40.61,42.1 40.96,41.75 | 40.96,41.75 | 40.96,41.75 43.66,39.05 51.91,39.05 52.55,39.69 v52.55,41.28 | v57.39,42.15 57.39,43.1 61.28,46.99 73.82,46.99 75.25,45.56 75.25,25.08 78.74,21.43 X2.17
XINT2  (via drill 0.6)
  Top 0.254: v52.55,38.42 55.09,38.42 55.56,38.42 56.99,39.85 58.66,41.51 v58.66,42.15
  Bottom 0.254: D1.16 40.45,41.15 43.18,38.42 v52.55,38.42 | v58.66,42.15 58.66,42.94 61.91,46.2 73.5,46.2 74.45,45.24 74.45,24.45 78.58,20.32 81.76,20.32 X2.18
XTAL1  (via drill 0.6)
  Top 0.254: v46.35,44.93 47.31,43.97 58.74,43.97 59.95,42.76 v59.95,42.13 v59.94,42.13 B1.2 | v46.35,44.93
  Bottom 0.254: D1.24 46.12,43.1 46.12,44.69 46.28,44.85 v46.35,44.93 | C1.2 61.12,43.34 v59.95,42.13
XTAL2  (via drill 0.6)
  Top 0.254: 69.22,43.66 68.1,44.77 47.94,44.77 v46.35,46.36 | 69.22,43.66 69.27,43.6 | 69.22,43.66 69.53,43.34 v69.53,42.23 69.53,39.05 69.6,39.12 B1.1
  Bottom 0.254: v46.35,46.36 45.8,46.36 45.32,45.88 45.32,43.1 45.4,43.02 45.38,43 D1.23 | v69.53,42.23 68.42,43.34 C2.2

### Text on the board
tPlace: Top
bPlace: Bottom
bDocu: Remote | X | Version 3.33 Final 10.08 | B. Wörndl-A. / M. Dullnig | www.ftkl.at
